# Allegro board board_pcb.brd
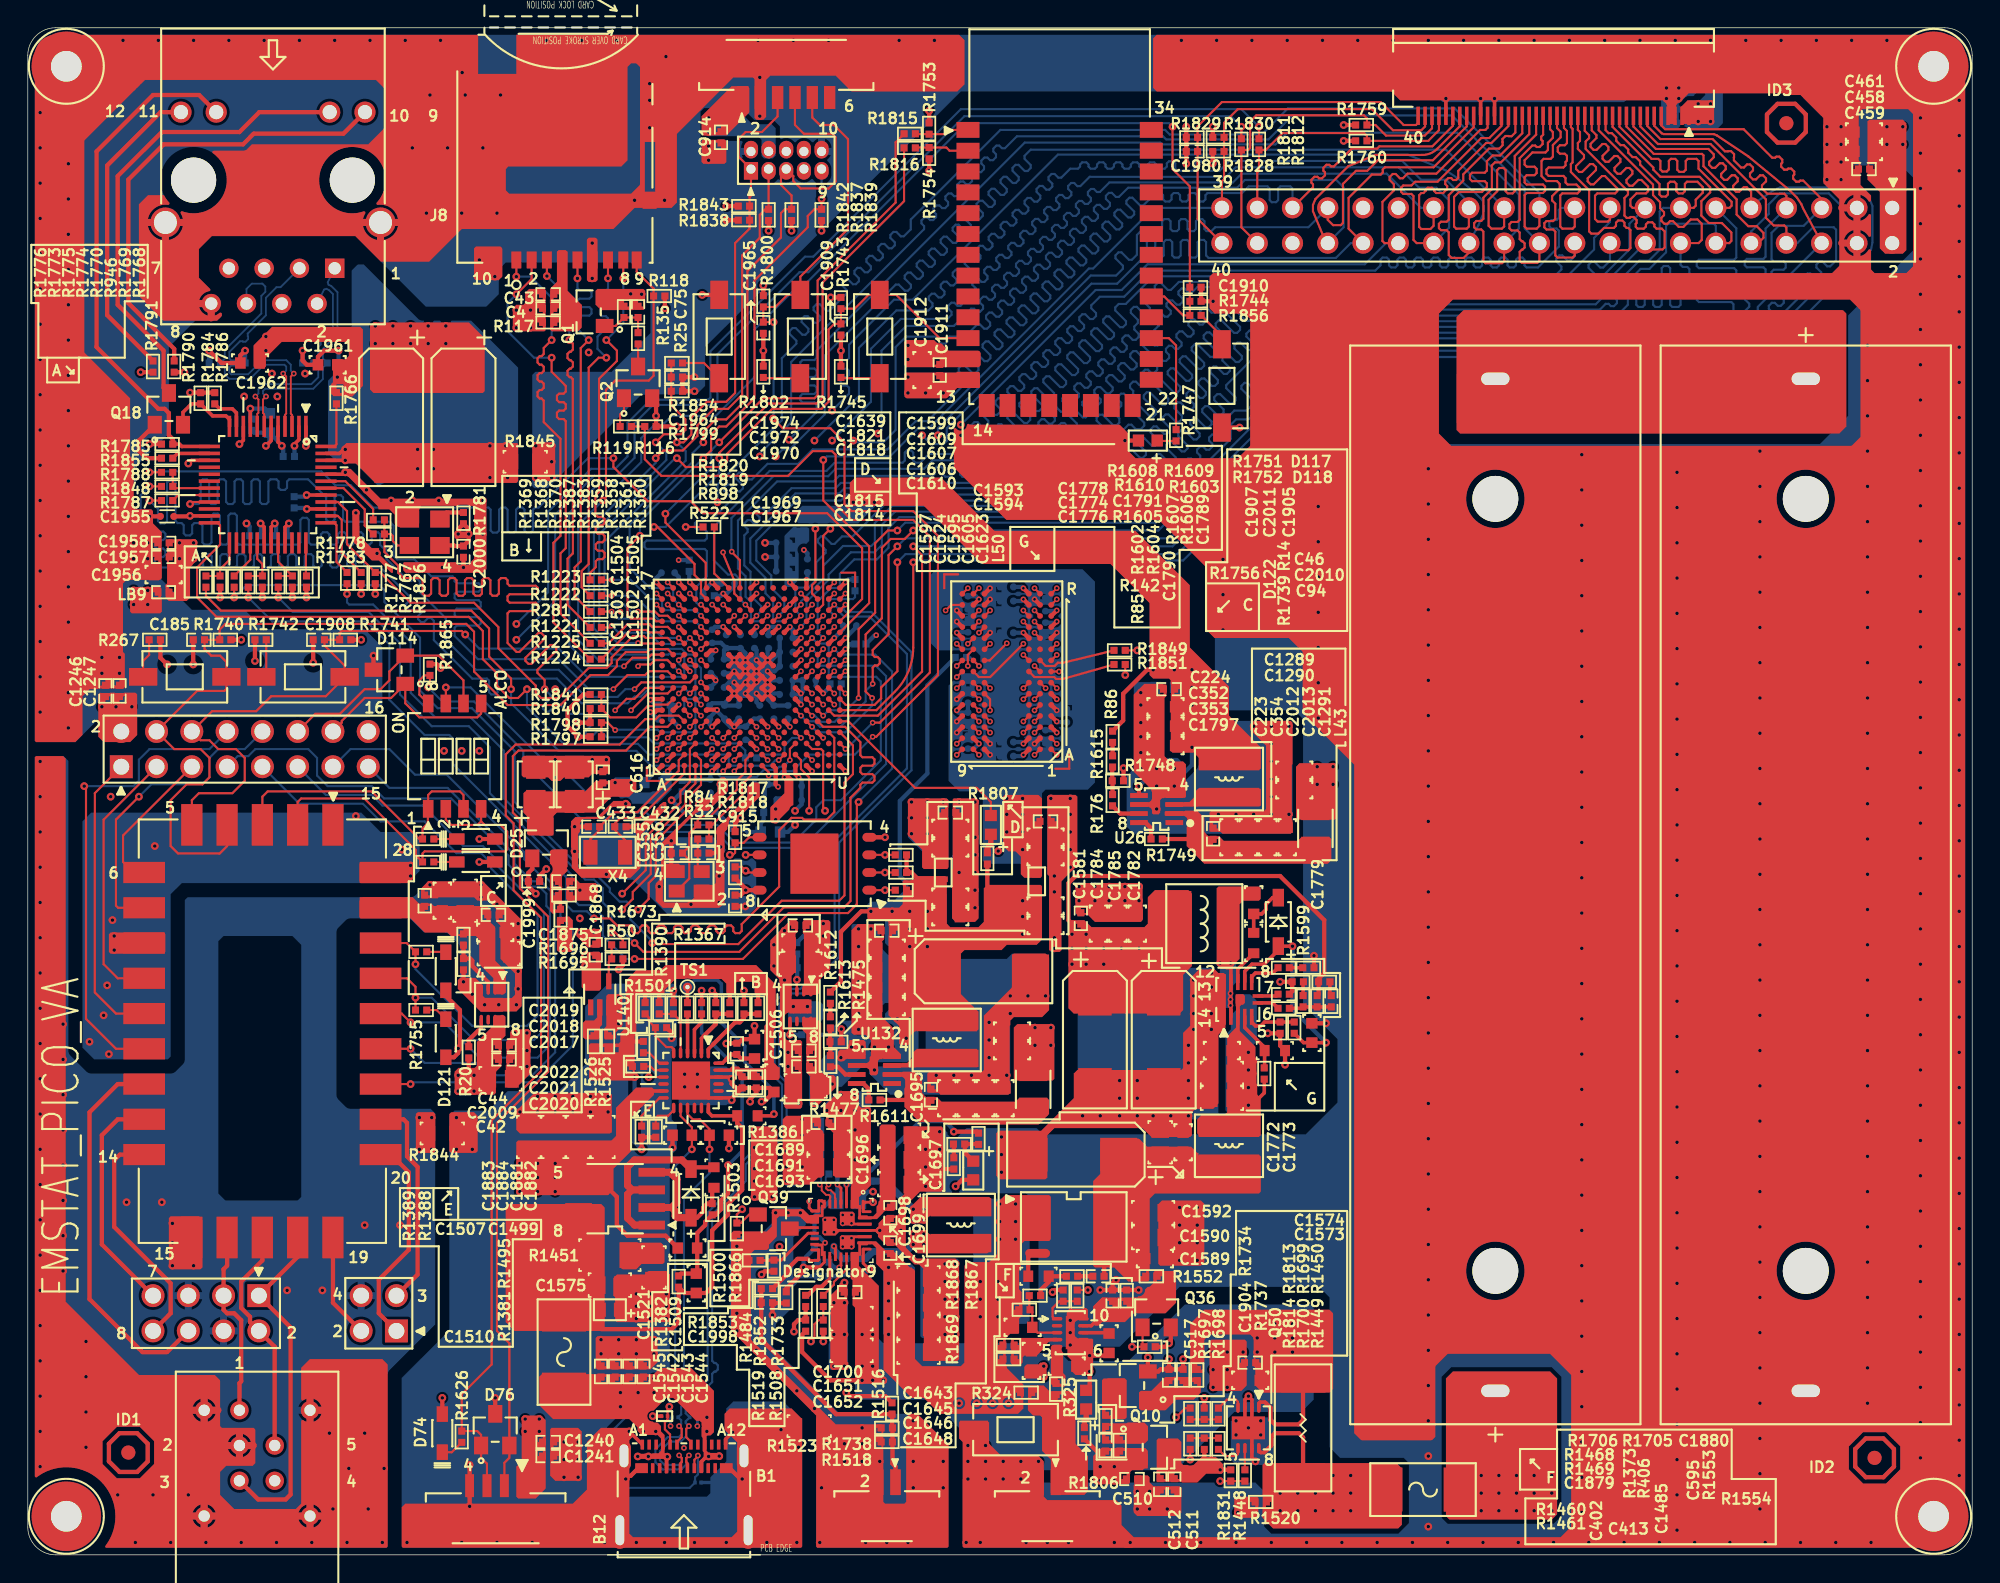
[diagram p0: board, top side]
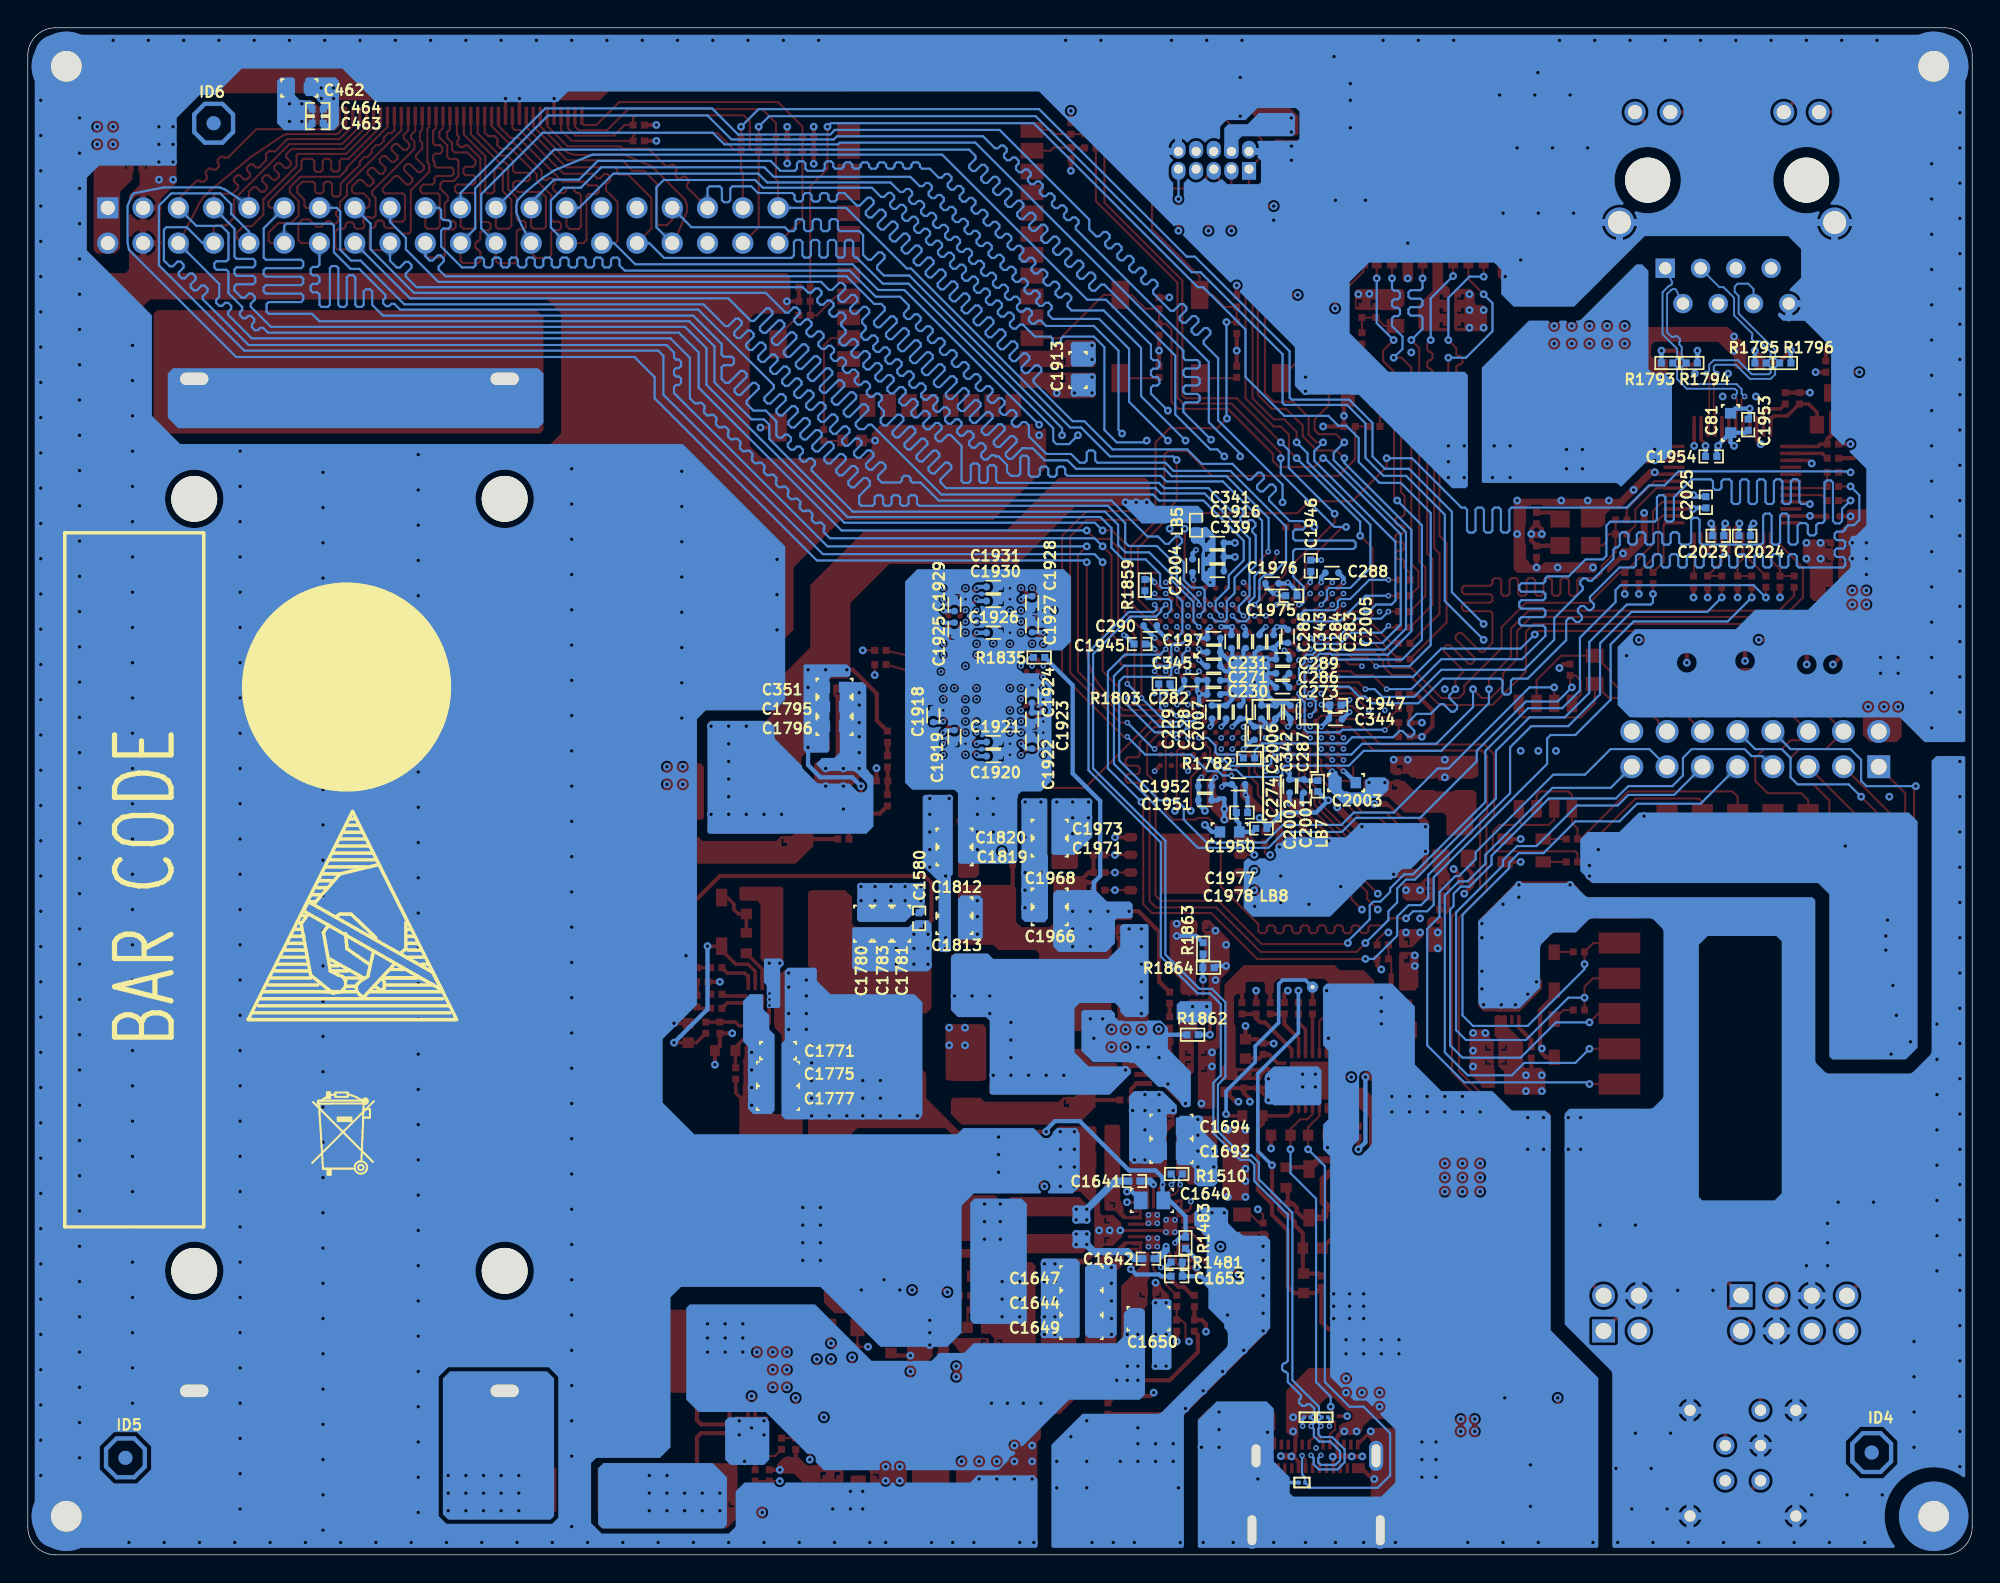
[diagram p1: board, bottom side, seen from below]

Outline 140 x 110 mm; copper layers: TOP, GND02, ART03, GND04, POWER05, ART06, GND07, ART08, GND09, BOTTOM. Coordinates in mm from the lower left corner of the outline.
Outline path: 0,108 0,2 arc(0.59,0.59) 2,0 138,0 arc(139.41,0.59) 140,2 140,108 arc(139.41,109.41) 138,110 2,110 arc(0.59,109.41) 0,108

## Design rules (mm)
constraint set DEFAULT: min track width 0.152
net group DIFF-USB: nets USB3_DM USB3_DP
net group DIFFPAIR0: nets RX+ RX-
net group DIFFPAIR1: nets TX+ TX-
net group DIFFPAIR2: nets BQ_DN BQ_DP
net group DIFFRX1_: nets RX1_N RX1_P
net group DIFFRX2_: nets RX2_N RX2_P
net group DIFFTX1_: nets TX1_N TX1_P
net group DIFFTX2_: nets TX2_N TX2_P
net group ETH_MDIO: nets ETH_MDIO N16775135
net group ETH_RMII_RXD0: nets ETH_RMII_RXD0 N16774923
net group ETH_RMII_RXD1: nets ETH_RMII_RXD1 N16774927
net group ETH_RMII_RXDV: nets ETH_RMII_RXDV N16776183
net group ETH_RMII_TXD0: nets ETH_RMII_TXD0 N16778460
net group FMC_A12: nets FMC_A12 N16908117
net group FMC_SDCKE0: nets FMC_SDCKE0 N16908318
net group PHY_INT: nets N16774766 PHY_INT
net group SDIO0_CCLK_OUT: nets N8887240 SDIO0_CCLK_OUT
net group SDIO0_CCMD: nets N8887398 SDIO0_CCMD
net group SDIO0_CDATA0: nets N8887325 SDIO0_CDATA0
net group SDIO0_CDATA1: nets N8887321 SDIO0_CDATA1
net group SDIO0_CDATA2: nets N8887299 SDIO0_CDATA2
net group SDIO0_CDATA3: nets N8887317 SDIO0_CDATA3
net group BUS_FMC_A: nets FMC_A0 FMC_A1 FMC_A2 FMC_A3 FMC_A4 FMC_A5 FMC_A6 FMC_A7 FMC_A8 FMC_A9 FMC_A10 FMC_A11 FMC_A14/FMC_BA0 FMC_A15/FMC_BA1 FMC_SDCLK FMC_SDNCAS FMC_SDNE0 FMC_SDNRAS FMC_SDNWE
net group ETH_RMII_CLK: nets ETH_RMII_CLK N16776304 N16872883
net group ETH_RMII_TXD1: nets ETH_RMII_TXD1 ETH_RMII_TXD1-1 N16778536
net group POWER: nets 1V2 3V3 3V9 5V0 AGND AVDD1V8 BQ_AGND GAUGE_PULLUP GND GND_SIGNAL N14944 N8915420 N8916004 N16783015 N16783029 N16886716 PHY_3V3 VBAT VBUS VBUS_MAX VBUS_MIN VBUS_OUT VCC_COMB VCC_SYS VCCD VDD1V2 VDD_MCU VDD_SDRAM VDDA3V3 VDDD VDDIO3V3_SD

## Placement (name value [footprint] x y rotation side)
C4  1uF  [SC0402]  37.47 89.79 180 top
C42  22uF  [SC0805]  34.04 34.29 0 top
C43  100nF  [SC0402]  37.47 90.81 180 top
C44  100nF  [SC0402]  34.29 36.7 180 top
C46  100nF  [SC0402]  33.53 46.1 180 top
C75  1uF  [SC0402]  43.94 89.53 270 top
C81  22uF  [SC0603]  17.4 81.53 270 bottom
C94  10uF  [SC0805]  33.91 43.31 0 top
C185  100nF  [SC0402]  12.32 65.91 180 top
C197  4.7uF  [SC0402-BGA]  54.61 66.04 180 bottom
C223  100nF  [SC0402]  85.34 51.94 270 top
C224  100nF  [SC0402]  82.17 62.36 0 top
C228  100nF  [SC0402-BGA]  53.72 60.71 270 bottom
C229  100nF  [SC0402-BGA]  54.74 60.71 270 bottom
C230  100nF  [SC0402-BGA]  54.61 61.98 0 bottom
C231  100nF  [SC0402-BGA]  54.61 64.01 0 bottom
C271  100nF  [SC0402-BGA]  54.61 62.99 0 bottom
C273  100nF  [SC0402-BGA]  49.66 62.48 180 bottom
C274  100nF  [SC0402-BGA]  51.69 59.18 90 bottom
C282  100nF  [SC0402-BGA]  56.26 62.99 180 bottom
C283  100nF  [SC0402-BGA]  50.29 65.79 90 bottom
C284  100nF  [SC0402-BGA]  51.31 65.79 90 bottom
C285  100nF  [SC0402-BGA]  53.34 65.79 90 bottom
C286  100nF  [SC0402-BGA]  49.66 63.5 180 bottom
C287  100nF  [SC0402-BGA]  49.1 60.71 270 bottom
C288  100nF  [SC0402-BGA]  46.1 70.74 0 bottom
C289  100nF  [SC0402-BGA]  49.66 64.52 180 bottom
C290  100nF  [SC0402-BGA]  59.18 66.93 0 bottom
C332  100uF  [SC7343]  26.16 81.79 270 top
C339  100nF  [SC0402-BGA]  54.36 70.87 0 bottom
C341  2.2uF  [SC0402-BGA]  54.36 72.9 180 bottom
C342  100nF  [SC0402-BGA]  50.16 60.71 270 bottom
C343  100nF  [SC0402-BGA]  52.32 65.79 90 bottom
C344  100nF  [SC0402-BGA]  45.85 60.2 180 bottom
C345  100nF  [SC0402-BGA]  54.61 65.02 0 bottom
C351  22uF  [SC0603]  81.92 62.48 180 bottom
C352  22uF  [SC0603]  81.92 61.09 180 top
C353  22uF  [SC0603]  81.92 59.69 180 top
C354  1uF  [SC0603]  86.49 51.69 270 top
C355  22pF  [SC0402]  46.74 50.55 0 top
C356  22pF  [SC0402]  48.64 50.55 180 top
C402  100nF  [SC0603]  72.26 13.97 270 top
C413  100nF  [SC0603]  74.8 13.59 0 top
C432  6pF  [SC0402]  42.67 52.45 180 top
C433  6pF  [SC0402]  40.77 52.45 0 top
C458  100nF  [SC0603]  132.21 101.09 0 top
C459  1uF  [SC0402]  132.21 99.82 180 top
C461  10uF  [SC0603]  132.21 102.49 180 top
C462  10uF  [SC0603]  120.45 105.66 180 bottom
C463  1uF  [SC0402]  119.13 103.12 180 bottom
C464  100nF  [SC0402]  119.13 104.14 0 bottom
C510  100nF  [SC0402]  79.5 5.46 0 top
C511  1uF  [SC0402]  82.55 5.08 270 top
C512  100nF  [SC0402]  81.53 5.08 270 top
C517  100nF  [SC0402]  82.17 12.95 90 top
C595  100nF  [SC0402]  78.11 18.67 90 top
C616  100nF  [SC0402]  41.4 56.01 270 top
C914  100nF  [SC0402]  49.91 102.11 90 top
C915  100nF  [SC0402]  50.93 47.12 270 top
C1240  1uF  [SC0402]  37.47 8.13 180 top
C1241  100nF  [SC0402]  37.47 7.11 0 top
C1246  1uF  [SC0402]  5.59 62.23 270 top
C1247  100nF  [SC0402]  6.6 62.23 90 top
C1289  22uF  [SC0603]  91.19 56.52 180 top
C1290  1uF  [SC0603]  91.19 55.12 0 top
C1291  22uF  [SC0603]  90.68 51.69 90 top
C1485  1uF  [SC0603]  77.85 15.24 90 top
C1499  390pF  [SC0603]  49.78 30.23 180 top
C1502  100nF  [SC0402]  52.45 34.04 90 top
C1503  100nF  [SC0402]  51.44 34.04 90 top
C1504  100nF  [SC0402]  51.05 36.45 270 top
C1505  1uF  [SC0603]  52.32 36.45 270 top
C1506  1uF  [SC0603]  53.72 34.04 90 top
C1507  390pF  [SC0603]  47.12 30.23 0 top
C1509  1uF  [SC0603]  48.13 19.56 90 top
C1510  1uF  [SC0603]  47.5 22.1 0 top
C1521  4.7uF  [SC0805]  45.09 20.7 270 top
C1542  10nF  [SC0402]  42.29 13.21 270 top
C1543  10nF  [SC0402]  43.31 13.21 270 top
C1544  10nF  [SC0402]  44.32 13.21 270 top
C1545  10nF  [SC0402]  41.27 13.21 270 top
C1573  1uF  [SC0603]  88.01 12.57 180 top
C1574  10nF  [SC0402]  88.01 13.84 0 top
C1575  4.7uF  [SC0805]  41.91 19.43 0 top
C1580  1uF  [SC0402]  75.82 45.85 90 bottom
C1581  100nF  [SC0402]  75.82 45.85 90 top
C1589  100nF  [SC0603]  81.15 21.34 180 top
C1590  10uF  [SC0805]  81.03 22.86 0 top
C1591  150uF  [SC7343]  75.31 28.83 180 top
C1592  10uF  [SC0805]  81.03 24.64 0 top
C1593  22uF  [SC0603]  70.87 37.72 180 top
C1594  1uF  [SC0603]  70.87 36.32 0 top
C1595  22uF  [SC0603]  67.56 32.89 90 top
C1597  100nF  [SC0402]  65.02 33.15 270 top
C1599  100nF  [SC0402]  61.85 44.96 0 top
C1605  22uF  [SC0603]  68.96 32.89 90 top
C1606  10uF  [SC0603]  61.85 40.89 180 top
C1607  10uF  [SC0603]  61.85 42.29 180 top
C1608  100uF  [SC7343]  68.96 42.04 0 top
C1609  10uF  [SC0603]  61.85 43.69 180 top
C1610  10uF  [SC0603]  61.85 39.5 180 top
C1623  22uF  [SC0603]  70.36 32.89 90 top
C1624  1uF  [SC0603]  66.17 32.89 270 top
C1639  100nF  [SC0402]  73.28 52.83 180 top
C1640  4.7uF  [SC0805]  59.05 25.53 0 bottom
C1641  47nF  [SC0402]  60.33 26.92 180 bottom
C1642  47nF  [SC0402]  59.31 21.34 180 bottom
C1643  10uF  [SC0805]  64.14 19.94 0 top
C1644  10uF  [SC0805]  64.14 18.16 0 bottom
C1645  10uF  [SC0805]  64.14 18.16 0 top
C1646  10uF  [SC0805]  64.14 16.38 0 top
C1647  10uF  [SC0805]  64.14 19.94 0 bottom
C1648  10uF  [SC0805]  64.14 14.61 0 top
C1649  10uF  [SC0805]  64.14 16.38 0 bottom
C1650  10uF  [SC0805]  59.31 17.02 180 bottom
C1651  10uF  [SC0805]  59.31 17.02 180 top
C1652  10uF  [SC0805]  59.31 14.73 180 top
C1653  1nF  [SC0402]  57.28 20.07 180 bottom
C1689  100nF  [SC0402]  57.28 31.11 180 top
C1691  10uF  [SC0805]  57.66 29.72 180 top
C1692  10uF  [SC0805]  57.66 29.08 180 bottom
C1693  10uF  [SC0805]  57.66 27.94 180 top
C1694  10uF  [SC0805]  57.66 30.86 180 bottom
C1695  10uF  [SC0805]  62.74 30.23 0 top
C1696  10uF  [SC0805]  62.74 28.45 0 top
C1697  10uF  [SC0805]  62.74 26.67 0 top
C1698  100nF  [SC0402]  62.1 24.64 270 top
C1699  100nF  [SC0402]  62.1 22.1 90 top
C1700  100nF  [SC0402]  59.18 18.92 180 top
C1771  1uF  [SC0603]  85.98 36.32 0 bottom
C1772  22uF  [SC0805]  81.53 29.72 90 top
C1773  1uF  [SC0603]  83.19 29.72 270 top
C1774  22uF  [SC0805]  85.98 34.67 180 top
C1775  22uF  [SC0805]  85.98 34.67 180 bottom
C1776  22uF  [SC0805]  85.98 32.89 180 top
C1777  22uF  [SC0805]  85.98 32.89 180 bottom
C1778  100nF  [SC0603]  85.98 36.32 0 top
C1779  100nF  [SC0603]  88.27 46.86 270 top
C1780  22uF  [SC0603]  79.88 45.47 90 bottom
C1781  22uF  [SC0603]  77.09 45.47 90 bottom
C1782  22uF  [SC0603]  79.88 45.47 90 top
C1783  22uF  [SC0603]  78.49 45.47 90 bottom
C1784  22uF  [SC0603]  77.09 45.47 90 top
C1785  22uF  [SC0603]  78.49 45.47 90 top
C1786  150uF  [SC7343]  76.83 36.96 270 top
C1788  150uF  [SC7343]  81.79 36.96 270 top
C1789  100nF  [SC0402]  93.85 39.88 90 top
C1790  100nF  [SC0603]  92.46 37.59 270 top
C1791  100nF  [SC0402]  90.42 40.39 180 top
C1795  22uF  [SC0603]  81.92 61.09 180 bottom
C1796  22uF  [SC0603]  81.92 59.69 180 bottom
C1797  22uF  [SC0603]  81.92 58.29 180 top
C1812  10uF  [SC0603]  73.28 46.74 0 bottom
C1813  22uF  [SC0603]  73.28 45.34 0 bottom
C1814  22uF  [SC0603]  73.28 45.34 0 top
C1815  1uF  [SC0603]  73.28 46.74 180 top
C1818  22uF  [SC0603]  73.28 50.29 0 top
C1819  22uF  [SC0603]  73.28 50.29 0 bottom
C1820  10uF  [SC0603]  73.28 51.69 0 bottom
C1821  1uF  [SC0603]  73.28 51.69 180 top
C1868  100nF  [SC0402]  40.89 43.59 90 top
C1875  100nF  [SC0402]  38.61 48.51 180 top
C1879  220nF  [SC0603]  71.63 16.38 180 top
C1880  47nF  [SC0402]  77.09 20.07 180 top
C1881  10uF  [SC0805]  39.62 30.1 90 top
C1882  10uF  [SC0805]  41.4 30.1 90 top
C1883  10uF  [SC0805]  36.07 30.1 90 top
C1884  10uF  [SC0805]  37.85 30.1 90 top
C1904  1uF  [SC0402]  77.6 7.87 90 top
C1905  10uF  [SC0805]  31.5 47.12 90 top
C1907  100nF  [SC0402]  28.57 47.12 270 top
C1908  100nF  [SC0402]  20.95 65.91 180 top
C1909  100nF  [SC0402]  58.55 88.27 270 top
C1910  100nF  [SC0402]  84.07 91.31 0 top
C1911  100nF  [SC0402]  65.66 85.34 90 top
C1912  10uF  [SC0603]  64.39 85.34 270 top
C1913  10uF  [SC0603]  64.39 85.34 270 bottom
C1916  470nF  [SC0402-BGA]  54.36 71.88 180 bottom
C1918  100nF  [SC0402-BGA]  74.8 60.45 90 bottom
C1919  100nF  [SC0402-BGA]  73.28 58.93 270 bottom
C1920  100nF  [SC0402-BGA]  70.48 57.53 180 bottom
C1921  100nF  [SC0402-BGA]  70.48 58.55 180 bottom
C1922  100nF  [SC0402-BGA]  67.69 58.55 90 bottom
C1923  100nF  [SC0402-BGA]  67.69 60.2 270 bottom
C1924  100nF  [SC0402-BGA]  67.69 61.85 90 bottom
C1925  100nF  [SC0402-BGA]  73.28 66.67 270 bottom
C1926  100nF  [SC0402-BGA]  70.48 66.42 180 bottom
C1927  100nF  [SC0402-BGA]  67.69 66.93 90 bottom
C1928  100nF  [SC0402-BGA]  67.69 68.58 270 bottom
C1929  100nF  [SC0402-BGA]  73.28 68.45 90 bottom
C1930  100nF  [SC0402-BGA]  70.48 68.71 180 bottom
C1931  100nF  [SC0402-BGA]  70.48 69.72 180 bottom
C1945  2.2uF  [SC0402]  59.94 65.61 180 bottom
C1946  2.2uF  [SC0402]  47.62 71.25 270 bottom
C1947  2.2uF  [SC0402]  45.85 61.21 180 bottom
C1950  470nF  [SC0402-BGA]  52.83 55.5 180 bottom
C1951  1uF  [SC0402-BGA]  55.24 54.36 0 bottom
C1952  100nF  [SC0402-BGA]  55.24 55.37 180 bottom
C1953  100nF  [SC0402]  16.13 81.41 90 bottom
C1954  100nF  [SC0402]  18.8 79.12 0 bottom
C1955  100nF  [SC0402-BGA]  10.03 74.8 0 top
C1956  10uF  [SC0603]  9.78 70.61 180 top
C1957  1uF  [SC0402]  9.78 71.88 180 top
C1958  100nF  [SC0402]  9.78 72.9 0 top
C1961  100nF  [SC0603]  21.59 85.72 180 top
C1962  100nF  [SC0603]  16 85.85 180 top
C1964  100nF  [SC0402]  46.74 84.84 0 top
C1965  100nF  [SC0402]  52.96 88.39 270 top
C1966  22uF  [SC0603]  66.42 45.97 0 bottom
C1967  22uF  [SC0603]  66.42 45.97 0 top
C1968  10uF  [SC0603]  66.42 47.37 0 bottom
C1969  1uF  [SC0603]  66.42 47.37 180 top
C1970  22uF  [SC0603]  66.42 50.93 0 top
C1971  22uF  [SC0603]  66.42 50.93 0 bottom
C1972  10uF  [SC0603]  66.42 52.32 0 top
C1973  1uF  [SC0603]  66.42 52.32 180 bottom
C1974  100nF  [SC0402]  66.42 53.47 180 top
C1975  1uF  [SC0402]  49.02 69.09 0 bottom
C1976  100nF  [SC0402-BGA]  50.42 69.98 180 bottom
C1977  1uF  [SC0402]  52.58 53.47 180 bottom
C1978  100nF  [SC0603]  53.47 52.07 180 bottom
C1980  100nF  [SC0402]  83.82 101.09 180 top
C1998  1nF  [SC0402]  53.21 18.16 0 top
C1999  100nF  [SC0402]  36.45 48.51 0 top
C2000  100nF  [SC0402]  31.37 72.26 90 top
C2001  4.7uF  [SC0402-BGA]  48.13 55.37 270 bottom
C2002  100nF  [SC0402-BGA]  49.15 55.37 90 bottom
C2003  100nF  [SC0603]  45.09 55.63 0 bottom
C2004  100nF  [SC0402-BGA]  56.13 71.25 270 bottom
C2005  100nF  [SC0402-BGA]  49.28 66.17 90 bottom
C2006  100nF  [SC0402-BGA]  51.18 60.71 270 bottom
C2007  100nF  [SC0402-BGA]  52.7 60.71 270 bottom
C2008  100uF  [SC7343]  31.37 81.79 270 top
C2009  1uF  [SC0402]  34.29 35.69 0 top
C2010  1uF  [SC0603]  33.66 44.83 180 top
C2011  1uF  [SC0603]  29.84 47.12 270 top
C2012  10uF  [SC0603]  87.88 51.69 90 top
C2013  10uF  [SC0603]  89.28 51.69 90 top
C2015  -  [CPH3225A]  36.58 55.5 90 top
C2016  -  [CPH3225A]  39.37 55.5 90 top
C2017  10uF  [SC0805]  55.63 42.55 180 top
C2018  1uF  [SC0603]  55.63 44.07 0 top
C2019  100nF  [SC0402]  55.63 45.34 0 top
C2020  22uF  [SC0805]  56.01 33.78 180 top
C2021  1uF  [SC0402]  55.88 35.18 180 top
C2022  100nF  [SC0402]  55.88 36.32 0 top
C2023  100nF  [SC0402]  18.29 73.41 180 bottom
C2024  100nF  [SC0402]  16.38 73.41 0 bottom
C2025  100nF  [SC0402]  19.18 75.82 90 bottom
D25  BAS70-05  [SOT23]  37.34 51.31 0 top
D74  BAT60BE6327  [HSOD323A]  29.84 8.76 270 top
D76  PSOT05C  [SOT23]  33.66 9.02 0 top
D96  uClamp2271P  [DFN16X10X050X2LEAD]  41.91 17.65 0 top
D97  NZH10C,115  [SOD123F]  47.75 26.04 270 top
D106  RClamp3371ZC  [DFN_060X030X025MM_2LEAD]  48.26 5.21 0 bottom
D107  RClamp3371ZC  [DFN_060X030X025MM_2LEAD]  45.85 9.99 180 top
D108  RClamp3371ZC  [DFN_060X030X025MM_2LEAD]  47.88 9.91 0 bottom
D109  RClamp3371ZC  [DFN_060X030X025MM_2LEAD]  46.61 9.91 180 bottom
D112  BAV16W  [SOD123]  90.04 45.59 90 top
D113  LSM0603412V  [SLED0603]  80.64 80.26 0 top
D114  PSOT05C  [SOT23]  26.04 63.75 90 top
D117  BAT60BE6327  [HSOD323A]  32.26 51.56 180 top
D118  BAT60BE6327  [HSOD323A]  32.26 49.91 180 top
D121  BAT60BE6327  [HSOD323A]  30.1 37.21 90 top
D122  BAT60BE6327  [HSOD323A]  30.1 42.04 90 top
D132  LSM0603412V  [SLED0603]  69.34 52.58 270 top
D133  LSM0603453V  [SLED0603]  76.2 11.18 270 top
D134  LSM0603453V  [SLED0603]  68.07 27.69 90 top
F1  SSQ8  [CRF1206-FX-R020ELF]  100.46 4.7 0 top
F4  SSQ8  [CRF1206-FX-R020ELF]  38.61 14.61 90 top
J1  FH12-40S-0.5SH(54)  [FPC-40P_05MM]  109.86 105.28 0 top
J2  2X20P_40P_2_54MM  [DIP_2X20X_254]  110.11 95.76 180 top
J3  -  [HR911105A]  17.65 97.03 0 top
J5  BAT_CONNECTOR  [BAT_CONNECTOR_18650]  105.66 48.26 270 top
J6  1.25T-1-WT-6A  [1P25MM-6PIN]  54.61 106.43 0 top
J7  BAT_CONNECTOR  [BAT_CONNECTOR_18650]  128.02 48.26 90 top
J8  DM3AT_SF_PEJM5  [HSDC10-1614B]  37.95 101.25 180 top
J56  -  [1P27MM-10PIN]  54.61 100.46 0 top
J63  1.25T-1-LT-4A  [4PIN-1P25MM]  33.69 3.53 0 top
J73  2012670005  [USB_C_24P]  47.24 4.66 0 top
J74  67996-104HLF  [2X2PIN_254MM]  25.27 17.4 90 top
J75  -  [EPG_0B_305_HLN]  16.51 6.6 270 top
J76  826632-4  [8PIN_254MM]  12.83 17.4 180 top
J78  67996-116HLF  [2X8PIN_254MM]  15.62 58.04 0 top
J85  1.25T-1-LT-2A  [2PIN_125MM]  61.85 3.68 180 top
J86  1.25T-1-LT-2A  [2PIN_125MM]  73.41 3.68 180 top
L10  1uH  [XEL4030]  86.49 55.88 90 top
L43  1uH  [SL1008H]  92.71 52.32 270 top
L50  1uH  [SL1008H]  72.39 33.53 270 top
L53  1uH  [XEL4030]  66.17 37.08 90 top
L54  1uH  [XEL4030]  67.18 23.75 90 top
L59  1uH  [XEL4030]  86.49 29.46 90 top
L60  1uH  [XAL5030]  84.71 45.47 180 top
L61  18nH  [PFL1005]  72.64 48.51 90 top
L63  18nH  [PFL1005]  65.91 49.15 90 top
LB5  BLM15HG102SN1D  [SL0402]  55.88 74.17 270 bottom
LB7  BLM15HG102SN1D  [SL0402]  47.12 55.37 90 bottom
LB8  BLM15HG102SN1D  [SL0402]  51.18 52.32 0 bottom
LB9  BLM15HG102SN1D  [SL0402]  9.78 69.34 0 top
M1  -  [HOLE87-197]  137.22 107.22 0 top
M2  -  [HOLE87-197]  2.78 107.22 0 top
M3  -  [HOLE87-197]  137.22 2.78 0 top
M4  -  [HOLE87-197]  2.78 2.78 0 top
NOREF  -  []  2 110 0 top
NOREF#2  -  []  162.9 151.25 0 top
NOREF#3  -  []  47.6 201.98 0 top
NOREF#4  -  [unnamed#2]  132.97 6.99 0 top
NOREF#5  -  []  158.62 225.3 0 top
NOREF#6  -  [unnamed#2]  126.62 103.12 0 top
NOREF#7  -  []  0 0 0 top
NOREF#8  -  []  140 2 0 top
NOREF#9  -  []  -53.9 -55.37 0 top
NOREF#10  -  [unnamed#2]  7.24 7.37 0 top
NOREF#11  -  []  0 0 0 top
NOREF#12  -  []  71.15 144.3 0 top
NOREF#13  -  []  116.1 45.54 180 bottom
NOREF#14  -  []  117.17 62.76 180 bottom
NOREF#15  -  [unnamed#2]  126.62 103.12 180 bottom
NOREF#16  -  []  132.26 49.02 90 bottom
NOREF#17  -  [unnamed#2]  132.97 6.99 180 bottom
NOREF#18  -  [unnamed#2]  7.24 7.37 180 bottom
NOREF#19  -  []  114.76 30.45 180 bottom
Q1  SI2305CDS-T1-GE3  [SOT23]  40.39 89.53 90 top
Q2  BSS806NE  [SOT23]  43.94 84.45 0 top
Q10  BSS806NE  [SOT23]  79.5 12.19 90 top
Q18  S8050LTI  [SOT23]  10.16 82.55 0 top
Q22  IRF9358TRPBF  [8-SOIC]  42.29 25.65 90 top
Q35  BSO080P03S H  [INF-PG-DSO-8-3_N]  75.31 23.62 0 top
Q36  BSS806NE  [SOT23]  81.28 17.53 0 top
Q39  BSS806NE  [SOT23]  53.72 23.5 270 top
Q50  SI2305CDS-T1-GE3  [SOT23]  81.15 7.75 270 top
R14  68K  [SR0402]  31.37 44.32 270 top
R20  10K  [SR0402]  31.75 36.2 90 top
R25  100  [SR0402]  43.94 87.63 270 top
R32  100  [SR0402]  48.64 51.56 0 top
R50  30K  [SR0402]  42.44 42.93 0 top
R84  1M  [SR0402]  48.64 52.58 0 top
R85  100K  [SR0402]  89.03 34.67 90 top
R86  100K  [SR0402]  78.11 58.93 270 top
R116  10K  [SR0402]  44.83 81.28 0 top
R117  10K  [SR0402]  37.47 88.77 180 top
R118  10K  [SR0402]  45.47 90.68 180 top
R119  2K  [SR0402]  43.05 81.28 0 top
R135  2K  [SR0402]  42.93 89.53 270 top
R142  49.9K  [SR0603]  89.79 36.32 0 top
R176  0  [SR0402]  78.11 54.36 90 top
R267  100  [SR0402]  9.14 65.91 0 top
R281  33  [SR0402]  40.89 67.94 0 top
R324  10K  [SR0402]  71.88 11.68 0 top
R325  4.7K  [SR0402]  74.04 11.94 90 top
R406  33  [SR0402]  75.56 18.67 270 top
R522  0  [SR0402]  49.02 74.04 0 top
R898  10K  [SR0402]  62.87 47.88 180 top
R946  120  [SR0402]  18.03 70.1 270 top
R1221  33  [SR0402]  40.89 66.8 0 top
R1222  33  [SR0402]  40.89 69.09 0 top
R1223  33  [SR0402]  40.89 70.23 0 top
R1224  33  [SR0402]  40.89 64.52 0 top
R1225  33  [SR0402]  40.89 65.66 0 top
R1358  5.1K  [SR0402]  50.55 39.37 90 top
R1359  2.43K  [SR0402]  49.53 39.37 90 top
R1360  5.1K  [SR0402]  52.58 39.37 90 top
R1361  1K  [SR0402]  51.56 39.37 270 top
R1367  0  [SR0402]  45.59 37.97 0 top
R1368  5.1K  [SR0402]  45.47 39.37 90 top
R1369  5.1K  [SR0402]  44.45 39.37 90 top
R1370  5.1K  [SR0402]  46.48 39.37 270 top
R1373  4.7K  [SR0402]  74.55 18.67 90 top
R1381  0  [SR0402]  49.28 24.89 270 top
R1382  10K  [SR0402]  46.86 19.68 90 top
R1383  1K  [SR0402]  48.51 39.37 90 top
R1386  49.9K  [SR0603]  51.82 31.62 0 top
R1387  1K  [SR0402]  47.5 39.37 90 top
R1388  2K  [SR0402]  45.21 30.48 270 top
R1389  2K  [SR0402]  44.2 30.48 270 top
R1390  2K  [SR0402]  44.32 36.58 90 top
R1446  0.01  [SR2512]  91.82 9.14 90 top
R1448  33  [SR0402]  87.63 5.71 90 top
R1449  33  [SR0402]  85.72 8 270 top
R1450  33  [SR0402]  85.72 10.16 90 top
R1451  5.6  [SR1206]  41.91 21.59 180 top
R1460  2K  [SR0402]  70.61 15.11 0 top
R1461  2K  [SR0402]  70.61 14.1 180 top
R1468  100K  [SR0402]  72.52 18.67 180 top
R1469  100K  [SR0402]  71.75 17.65 0 top
R1475  5.1K  [SR0402]  58.17 36.96 0 top
R1477  0  [SR0402]  57.78 35.56 90 top
R1481  6.04K  [SR0402]  57.28 21.08 180 bottom
R1483  100K  [SR0402]  56.64 22.48 270 bottom
R1484  180K  [SR0402]  54.61 18.54 270 top
R1495  49.9K  [SR0603]  49.4 27.18 270 top
R1500  12K  [SR0402]  52.32 21.21 0 top
R1501  2K  [SR0402]  43.94 35.18 0 top
R1503  10K  [SR0402]  51.05 23.5 270 top
R1508  10K  [SR0402]  57.28 16.51 90 top
R1510  0  [SR0402]  57.28 27.43 0 bottom
R1516  5.23K  [SR0402]  62.23 10.54 270 top
R1518  30K  [SR0402]  61.85 8.13 0 top
R1519  0  [SR0402]  56.01 16.51 90 top
R1520  0  [SR0402]  88.77 3.81 0 top
R1523  10  [SR0805]  56.26 9.27 180 top
R1525  10K  [SR0402]  41.78 36.98 90 top
R1526  100  [SR0402]  40.77 36.98 90 top
R1552  180K  [SR0402]  80.9 20.07 180 top
R1553  30K  [SR0402]  79.12 18.67 90 top
R1554  4.7K  [SR0402]  80.77 14.99 180 top
R1599  10  [SR0603]  88.27 44.07 90 top
R1602  4.7K  [SR0402]  90.17 37.97 270 top
R1603  4.7K  [SR0402]  93.34 41.27 0 top
R1604  4.7K  [SR0402]  91.19 37.97 270 top
R1605  12.7K  [SR0402]  90.42 39.37 0 top
R1606  22.1K  [SR0402]  92.84 39.88 90 top
R1607  2K  [SR0402]  91.82 39.88 90 top
R1608  10K  [SR0402]  90.42 42.29 180 top
R1609  4.7K  [SR0402]  92.2 42.29 0 top
R1610  1K  [SR0402]  91.44 41.27 180 top
R1611  4.7K  [SR0402]  60.96 32.77 180 top
R1612  22.1K  [SR0402]  57.78 40.13 270 top
R1613  1.5K  [SR0402]  57.78 38.35 90 top
R1615  2K  [SR0402]  78.11 57.15 270 top
R1626  4.7K  [SR0402]  31.24 8.51 90 top
R1673  33  [SR0402]  42.44 43.94 0 top
R1695  22.1K  [SR0402]  38.35 46.1 270 top
R1696  10K  [SR0402]  38.61 47.5 0 top
R1697  20K  [SR0402]  83.19 12.95 90 top
R1698  20K  [SR0402]  84.2 12.95 90 top
R1699  4.7K  [SR0402]  84.71 10.16 90 top
R1700  4.7K  [SR0402]  84.71 8 270 top
R1705  2K  [SR0402]  75.18 20.07 0 top
R1706  10  [SR0603]  72.77 20.07 180 top
R1733  33  [SR0402]  57.28 18.29 270 top
R1734  100  [SR0402]  77.6 9.65 90 top
R1737  2K  [SR0402]  78.61 7.87 90 top
R1738  10K  [SR0402]  61.85 9.14 180 top
R1739  10K  [SR0402]  31.37 42.55 270 top
R1740  10K  [SR0402]  14.22 65.91 180 top
R1741  10K  [SR0402]  22.86 65.91 180 top
R1742  100  [SR0402]  16.76 65.91 180 top
R1743  10K  [SR0402]  58.55 90.17 270 top
R1744  10K  [SR0402]  84.07 90.3 0 top
R1745  100  [SR0402]  58.55 85.22 90 top
R1747  470  [SR0402]  82.68 80.64 270 top
R1748  100K  [SR0402]  78.49 55.75 0 top
R1749  4.7K  [SR0402]  81.28 51.56 180 top
R1751  10K  [SR0402]  28.83 51.56 180 top
R1752  10K  [SR0402]  28.83 49.91 180 top
R1753  4.7K  [SR0402]  64.9 102.74 270 top
R1754  4.7K  [SR0402]  64.9 100.97 90 top
R1755  4.7K  [SR0402]  28.32 39.24 180 top
R1756  4.7K  [SR0402]  28.32 43.43 180 top
R1759  4.7K  [SR0402]  96.01 103 0 top
R1760  4.7K  [SR0402]  96.01 101.85 0 top
R1766  6.8K 1%  [SR0402]  22.23 83.31 90 top
R1767  10K  [SR0402]  24 70.36 270 top
R1768  10K  [SR0402]  20.07 70.1 270 top
R1769  10K  [SR0402]  19.05 70.1 270 top
R1770  10K  [SR0402]  16.89 70.1 90 top
R1773  10K  [SR0402]  13.84 70.1 270 top
R1774  120  [SR0402]  15.88 70.1 270 top
R1775  120  [SR0402]  14.86 70.1 270 top
R1776  120  [SR0402]  12.83 70.1 270 top
R1777  120  [SR0402]  22.99 70.36 270 top
R1778  51  [SR0402]  25.27 74.55 0 top
R1781  1K  [SR0402]  31.37 74.68 270 top
R1782  51  [SR0402]  52.07 57.4 180 bottom
R1783  51  [SR0402]  25.27 73.53 0 top
R1784  10K  [SR0402]  12.45 83.31 90 top
R1785  10K  [SR0402]  10.03 80.01 180 top
R1786  10K  [SR0402]  13.46 83.31 90 top
R1787  120  [SR0402]  10.03 75.95 0 top
R1788  120  [SR0402]  10.03 76.96 0 top
R1790  510  [SR0402]  10.54 85.6 90 top
R1791  510  [SR0402]  9.02 85.6 90 top
R1793  49.9  [SR0402]  21.97 85.85 180 bottom
R1794  49.9  [SR0402]  20.19 85.85 0 bottom
R1795  49.9  [SR0402]  15.24 85.85 180 bottom
R1796  49.9  [SR0402]  13.46 85.85 0 bottom
R1797  10K  [SR0402]  40.89 58.93 0 top
R1798  10K  [SR0402]  40.89 59.94 0 top
R1799  10K  [SR0402]  46.74 83.82 0 top
R1800  10K  [SR0402]  52.96 90.3 270 top
R1802  100  [SR0402]  52.96 85.22 90 top
R1803  10K  [SR0402]  58.17 62.74 180 bottom
R1806  1K  [SR0402]  76.07 8.76 90 top
R1807  1K  [SR0402]  69.09 50.16 90 top
R1811  0  [SR0402]  87.38 101.6 90 top
R1812  0  [SR0402]  88.65 101.6 90 top
R1813  0  [SR0402]  83.69 10.16 90 top
R1814  0  [SR0402]  83.69 8 270 top
R1815  0  [SR0402]  63.5 102.36 180 top
R1816  0  [SR0402]  63.5 101.35 180 top
R1817  10K  [SR0402]  50.93 51.69 270 top
R1818  10K  [SR0402]  50.93 49.15 90 top
R1819  10K  [SR0402]  62.87 49.15 180 top
R1820  10K  [SR0402]  62.87 50.42 180 top
R1826  10K  [SR0402]  25.02 70.36 270 top
R1828  10K  [SR0402]  85.72 101.09 0 top
R1829  10K  [SR0402]  83.82 102.11 180 top
R1830  10K  [SR0402]  85.72 102.11 0 top
R1831  4.7K  [SR0402]  86.61 5.71 270 top
R1835  10K  [SR0402]  67.18 64.64 180 bottom
R1837  10K  [SR0402]  54.99 96.52 90 top
R1838  10K  [SR0402]  51.56 96.14 180 top
R1839  10K  [SR0402]  57.15 96.52 90 top
R1840  10K  [SR0402]  40.89 61.98 0 top
R1841  10K  [SR0402]  40.89 60.96 180 top
R1842  10K  [SR0402]  53.34 96.52 90 top
R1843  10K  [SR0402]  51.56 97.16 0 top
R1844  10  [SR0805]  29.84 30.35 180 top
R1845  10  [SR0805]  35.81 78.74 180 top
R1848  0  [SR0402]  10.03 77.98 0 top
R1849  0  [SR0402]  78.61 65.15 180 top
R1851  0  [SR0402]  78.61 64.14 180 top
R1852  100  [SR0402]  56.01 18.29 270 top
R1853  1K  [SR0402]  53.21 19.18 180 top
R1854  2K  [SR0402]  46.74 85.85 0 top
R1855  4.7K  [SR0402]  10.03 78.99 0 top
R1856  4.7K  [SR0402]  84.07 89.28 0 top
R1859  10K  [SR0402]  59.56 69.85 270 bottom
R1862  10K  [SR0402]  56.13 37.47 180 bottom
R1863  100K  [SR0402]  55.37 43.69 270 bottom
R1864  25K  [SR0402]  54.99 42.29 180 bottom
R1865  10K  [SR0402]  28.96 63.75 270 top
R1866  10K  [SR0402]  53.72 20.83 90 top
R1867  2K  [SR0402]  68.45 29.97 90 top
R1868  2K  [SR0402]  67.06 29.59 0 top
R1869  1K  [SR0402]  66.67 28.19 270 top
S3  SKQYAAE010  [SMT2]  11.3 63.25 0 top
S4  SKQYAAE010  [SMT2]  71.12 9.02 180 top
S5  SKQYAAE010  [SMT2]  19.81 63.25 0 top
S6  SKQYAAE010  [SMT2]  61.34 87.76 90 top
S7  SKQYAAE010  [SMT2]  85.98 84.2 270 top
S8  -  [1571983-4]  30.73 57.53 0 top
S10  SKQYAAE010  [SMT2]  49.78 87.76 90 top
S11  SKQYAAE010  [SMT2]  55.63 87.76 90 top
TS1  TEST  [GND12]  47.5 40.89 180 top
U1  STM32H743XIH6  [BGA265_0R8_14X14]  52.07 63.25 0 top
U2  IS42S32800G-6BLI  [FBGA90_0R8_8X13]  70.48 63.63 90 top
U3  DM9161EP  [LQFP48-0M5-JL]  17.27 77.09 180 top
U4  ADP125ACPZ-R7  [CP-8-10]  33.4 39.62 180 top
U8  MP2229GQ  [QFN-14]  87.12 40.01 0 top
U26  MP2143DJ  [TSOT23-8]  81.28 53.72 90 top
U37  LTC2955IDDB-2  [DFN10DDB]  75.06 16 270 top
U77  W25Q256JVEIQ  [WSON_8P_8X6MM]  56.64 49.78 90 top
U117  CYPD3177-24LQXQ  [QFN_24P]  47.75 34.16 180 top
U128  LTC2943IDD#PBF  [DFN_8P]  87.88 9.14 180 top
U132  MP2143DJ  [TSOT23-8]  60.96 34.92 90 top
U133  BQ25792RQMR  [RQM0029A-MFG]  58.55 23.37 270 top
U134  EMSTAT PICO  [EMSTAT_PICO]  16.89 37.72 270 top
U135  HC-06  [HC_06_34]  74.3 96.39 0 top
U140  SN74LVC1G07DCK  [HSOT-SC70-DCK]  41.18 40.37 0 top
U141  ADP125ACPZ-R7  [CP-8-10]  55.63 39.5 180 top
X3  XC22M4-25.000-F18LJDTY  [SMD_2520]  47.62 48.51 0 top
X4  -  [HSX2-0302]  41.76 50.61 0 top
X5  SIT8208AC-23-33E-50.000000  [SMD_3225]  28.57 73.66 180 top

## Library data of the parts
C4 C42-C44 C46 C75 C81 C94 C185 C197 C223 C224 C228-C231 C271 C273 C274 C282-C290 C339 C341-C345 C351-C356 C402 C413 C432 C433 C458 C459 C461-C464 C510-C512 C517 C595 C616 C914 C915 C1240 C1241 C1246 C1247 C1289-C1291 C1485 C1499 C1502-C1507 C1509 C1510 C1521 C1542-C1545 C1573-C1575 C1580 C1581 C1589 C1590 C1592-C1595 C1597 C1599 C1605-C1607 C1609 C1610 C1623 C1624 C1639-C1653 C1689 C1691-C1700 C1771-C1785 C1789-C1791 C1795-C1797 C1812-C1815 C1818-C1821 C1868 C1875 C1879-C1884 C1904 C1905 C1907-C1913 C1916 C1918-C1931 C1945-C1947 C1950-C1958 C1961 C1962 C1964-C1978 C1980 C1998-C2007 C2009-C2013 C2017-C2025 = C_1
C332 C1591 C1608 C1786 C1788 C2008 = CAP-OS
C2015 C2016 = CAP-OS-CON-F13_0
D25 = BAT54C_0
D74 D112 D113 D117 D118 D121 D122 D132-D134 = D_A_0
D76 D114 = D2-3_D
D96 D97 = DIODE ZENER
D106-D109 = RClamp3371ZC
F1 F4 = FUSE2
J1 = CON-FPC-40P_SMT_MOVEDOWN0_0
J2 = CON-LCD_2X20P_40P_2_54MM_TC_0
J3 = CN-NET_T_RJ45_HR911105A_HIDE_0
J5 J7 = BAT_CONNECTOR
J6 = 1_0.25T-1-LT-8A
J8 = SIMM10S4_B_0
J56 = 1P27MM-10PIN
J63 = 1.25T-1-LT-4A
J73 = 2012670005
J74 = Header 2X2
J75 = EPG_0B_305_HLN_0
J76 = Header 8
J78 = Header 8X2
J85 J86 = KF2EDGR-2.54
L10 L43 L50 L53 L54 L59-L61 L63 = IND
LB5 LB7-LB9 = LB_0
M1-M4 = HOLE-8STARS_2
Q1 Q50 = FETP-GSD_0
Q2 Q10 Q36 Q39 = NTR4503N
Q18 = 2N2222
Q22 = MOSFET_N_GDS_0
Q35 = BSO201SP H
R14 R20 R84-R86 R116-R119 R135 R142 R176 R324 R325 R406 R522 R898 R1358-R1361 R1367-R1370 R1373 R1381-R1383 R1386-R1390 R1448-R1451 R1460 R1461 R1468 R1469 R1475 R1477 R1483 R1484 R1495 R1500 R1501 R1503 R1508 R1510 R1516 R1519 R1520 R1523 R1525 R1552 R1554 R1599 R1602-R1613 R1615 R1626 R1673 R1695-R1700 R1705 R1706 R1733 R1737-R1741 R1743 R1744 R1748 R1749 R1751-R1756 R1759 R1760 R1766-R1770 R1773 R1778 R1781 R1784-R1786 R1790 R1791 R1793-R1800 R1803 R1806 R1807 R1811-R1820 R1826 R1828-R1831 R1835 R1837-R1845 R1853-R1856 R1859 R1862-R1869 = R
R25 R32 R50 R267 R1446 R1481 R1518 R1526 R1553 R1734 R1742 R1745 R1747 R1802 R1852 = R_0
R281 R1221-R1225 = R: signal model: RC0402FR-0733RL_33
R946 R1774-R1777 R1787 R1788 = R: signal model: RC0402FR-07120RL_120
R1782 R1783 = R: signal model: RC0402FR-0751RL_51
R1848 R1849 R1851 = R: signal model: RC0402JR_070RL_0
S3-S7 S10 S11 = SW_PB_SPST
S8 = SW DIP-6_0
TS1 = TEST
U1 = STM32H7_TFBGA265_18
U2 = IS42S32800G-6BLI_TF-BGA-90_2
U3 = U-DM9161_QPF48-0_1
U4 U141 = ADP125ACPZ-R7_0
U8 = MP2229GQ
U26 U132 = MP2143_0
U37 = LTC2955IDDB-DFN10DDB_0
U77 = N25Q032A11ESE40F_0
U117 = CYPD3177-24LQXQ
U128 = LTC2943IDD#PBF
U133 = BQ25792RQMR
U134 = EmStat pico_0
U135 = HC-06_0
U140 = SN74LVC1G07DCK
X3 = X_B_0
X4 = X_0_HSX2-0302_32.768KHZ
X5 = TMP_162231

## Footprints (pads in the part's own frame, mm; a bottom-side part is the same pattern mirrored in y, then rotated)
1P25MM-6PIN
  rect 2.108x2.997 smd: (-5.675,1.45) (5.675,1.45)
  rect 0.813x1.651 smd: 1(-3.125,-1.45) 2(-1.875,-1.45) 3(-0.625,-1.45) 4(0.625,-1.45) 5(1.875,-1.45) 6(3.125,-1.45)
1P27MM-10PIN
  rect 1.016x1.27 hole 0.66: 1(-2.54,-0.635)
  oval 1.016x1.27 hole 0.66: 2(-2.54,0.635) 3(-1.27,-0.635) 4(-1.27,0.635) 5(0,-0.635) 6(0,0.635) 7(1.27,-0.635) 8(1.27,0.635) 9(2.54,-0.635) 10(2.54,0.635)
2PIN_125MM
  rect 2.108x3.251 smd: (-3.175,1.45) (3.175,1.45)
  rect 0.762x1.854 smd: 1(-0.625,-1.55) 2(0.625,-1.55)
2X2PIN_254MM
  rect 1.651x1.651 hole 1.143: 1(-1.27,-1.27)
  round 1.651 hole 1.143: 2(-1.27,1.27) 3(1.27,-1.27) 4(1.27,1.27)
2X8PIN_254MM
  rect 1.651x1.651 hole 1.143: 1(-8.89,-1.27)
  round 1.651 hole 1.143: 2(-8.89,1.27) 3(-6.35,-1.27) 4(-6.35,1.27) 5(-3.81,-1.27) 6(-3.81,1.27) 7(-1.27,-1.27) 8(-1.27,1.27) 9(1.27,-1.27) 10(1.27,1.27) 11(3.81,-1.27) 12(3.81,1.27) 13(6.35,-1.27) 14(6.35,1.27) 15(8.89,-1.27) 16(8.89,1.27)
4PIN-1P25MM
  rect 2.159x2.997 smd: (-4.425,-1.45) (4.425,-1.45)
  rect 0.635x1.651 smd: 1(1.875,1.45) 2(0.625,1.45) 3(-0.625,1.45) 4(-1.875,1.45)
8-SOIC
  rect 0.635x1.905 smd: 1(-1.905,-2.632) 2(-0.635,-2.632) 3(0.635,-2.632) 4(1.905,-2.632) 5(1.905,2.632) 6(0.635,2.632) 7(-0.635,2.632) 8(-1.905,2.632)
8PIN_254MM
  rect 1.651x1.651 hole 1.143: 1(-3.81,-1.27)
  round 1.651 hole 1.143: 2(-3.81,1.27) 3(-1.27,-1.27) 4(-1.27,1.27) 5(1.27,-1.27) 6(1.27,1.27) 7(3.81,-1.27) 8(3.81,1.27)
1571983-4
  rect 0.762x1.27 smd: 1(-1.905,-3.795) 2(-0.635,-3.795) 3(0.635,-3.795) 4(1.905,-3.795) 5(1.905,3.795) 6(0.635,3.795) 7(-0.635,3.795) 8(-1.905,3.795)
BAT_CONNECTOR_18650
  round 3.302 hole 3.302 unplated: (-27.805,0) (27.805,0)
  oval 1.397x2.54 hole 0.889x2.032: 1(36.45,0) 2(-36.45,0)
BGA265_0R8_14X14
  round 0.406 smd: A1(-6.4,-6.4) A2(-6.4,-5.6) A3(-6.4,-4.8) A4(-6.4,-4) A5(-6.4,-3.2) A6(-6.4,-2.4) A7(-6.4,-1.6) A8(-6.4,-0.8) A9(-6.4,0) A10(-6.4,0.8) A11(-6.4,1.6) A12(-6.4,2.4) A13(-6.4,3.2) A14(-6.4,4) A15(-6.4,4.8) A16(-6.4,5.6) A17(-6.4,6.4) B1(-5.6,-6.4) B2(-5.6,-5.6) B3(-5.6,-4.8) B4(-5.6,-4) B5(-5.6,-3.2) B6(-5.6,-2.4) B7(-5.6,-1.6) B8(-5.6,-0.8) B9(-5.6,0) B10(-5.6,0.8) B11(-5.6,1.6) B12(-5.6,2.4) B13(-5.6,3.2) B14(-5.6,4) B15(-5.6,4.8) B16(-5.6,5.6) B17(-5.6,6.4) C1(-4.8,-6.4) C2(-4.8,-5.6) C3(-4.8,-4.8) C4(-4.8,-4) C5(-4.8,-3.2) C6(-4.8,-2.4) C7(-4.8,-1.6) C8(-4.8,-0.8) C9(-4.8,0) C10(-4.8,0.8) C11(-4.8,1.6) C12(-4.8,2.4) C13(-4.8,3.2) C14(-4.8,4) C15(-4.8,4.8) C16(-4.8,5.6) C17(-4.8,6.4) D1(-4,-6.4) D2(-4,-5.6) D3(-4,-4.8) D4(-4,-4) D5(-4,-3.2) D6(-4,-2.4) D7(-4,-1.6) D8(-4,-0.8) D9(-4,0) D10(-4,0.8) D11(-4,1.6) D12(-4,2.4) D13(-4,3.2) D14(-4,4) D15(-4,4.8) D16(-4,5.6) D17(-4,6.4) E1(-3.2,-6.4) E2(-3.2,-5.6) E3(-3.2,-4.8) E4(-3.2,-4) E5(-3.2,-3.2) E6(-3.2,-2.4) E7(-3.2,-1.6) E8(-3.2,-0.8) E9(-3.2,0) E10(-3.2,0.8) E11(-3.2,1.6) E12(-3.2,2.4) E13(-3.2,3.2) E14(-3.2,4) E15(-3.2,4.8) E16(-3.2,5.6) E17(-3.2,6.4) F1(-2.4,-6.4) F2(-2.4,-5.6) F3(-2.4,-4.8) F4(-2.4,-4) F5(-2.4,-3.2) F13(-2.4,3.2) F14(-2.4,4) F15(-2.4,4.8) F16(-2.4,5.6) F17(-2.4,6.4) G1(-1.6,-6.4) G2(-1.6,-5.6) G3(-1.6,-4.8) G4(-1.6,-4) G5(-1.6,-3.2) G7(-1.6,-1.6) G8(-1.6,-0.8) G9(-1.6,0) G10(-1.6,0.8) G11(-1.6,1.6) G13(-1.6,3.2) G14(-1.6,4) G15(-1.6,4.8) G16(-1.6,5.6) G17(-1.6,6.4) H1(-0.8,-6.4) H2(-0.8,-5.6) H3(-0.8,-4.8) H4(-0.8,-4) H5(-0.8,-3.2) H7(-0.8,-1.6) H8(-0.8,-0.8) H9(-0.8,0) H10(-0.8,0.8) H11(-0.8,1.6) H13(-0.8,3.2) H14(-0.8,4) H15(-0.8,4.8) H16(-0.8,5.6) H17(-0.8,6.4) J1(0,-6.4) J2(0,-5.6) J3(0,-4.8) J4(0,-4) J5(0,-3.2) J7(0,-1.6) J8(0,-0.8) J9(0,0) J10(0,0.8) J11(0,1.6) J13(0,3.2) J14(0,4) J15(0,4.8) J16(0,5.6) J17(0,6.4) K1(0.8,-6.4) K2(0.8,-5.6) K3(0.8,-4.8) K4(0.8,-4) K5(0.8,-3.2) K7(0.8,-1.6) K8(0.8,-0.8) K9(0.8,0) K10(0.8,0.8) K11(0.8,1.6) K13(0.8,3.2) K14(0.8,4) K15(0.8,4.8) K16(0.8,5.6) K17(0.8,6.4) L1(1.6,-6.4) L2(1.6,-5.6) L3(1.6,-4.8) L4(1.6,-4) L5(1.6,-3.2) L7(1.6,-1.6) L8(1.6,-0.8) L9(1.6,0) L10(1.6,0.8) L11(1.6,1.6) L13(1.6,3.2) L14(1.6,4) L15(1.6,4.8) L16(1.6,5.6) L17(1.6,6.4) M1(2.4,-6.4) M2(2.4,-5.6) M3(2.4,-4.8) M4(2.4,-4) M5(2.4,-3.2) M13(2.4,3.2) M14(2.4,4) M15(2.4,4.8) M16(2.4,5.6) M17(2.4,6.4) N1(3.2,-6.4) N2(3.2,-5.6) N3(3.2,-4.8) N4(3.2,-4) N5(3.2,-3.2) N6(3.2,-2.4) N7(3.2,-1.6) N8(3.2,-0.8) N9(3.2,0) N10(3.2,0.8) N11(3.2,1.6) N12(3.2,2.4) N13(3.2,3.2) N14(3.2,4) N15(3.2,4.8) N16(3.2,5.6) N17(3.2,6.4) P1(4,-6.4) P2(4,-5.6) P3(4,-4.8) P4(4,-4) P5(4,-3.2) P6(4,-2.4) P7(4,-1.6) P8(4,-0.8) P9(4,0) P10(4,0.8) P11(4,1.6) P12(4,2.4) P13(4,3.2) P14(4,4) P15(4,4.8) P16(4,5.6) P17(4,6.4) R1(4.8,-6.4) R2(4.8,-5.6) R3(4.8,-4.8) R4(4.8,-4) R5(4.8,-3.2) R6(4.8,-2.4) R7(4.8,-1.6) R8(4.8,-0.8) R9(4.8,0) R10(4.8,0.8) R11(4.8,1.6) R12(4.8,2.4) R13(4.8,3.2) R14(4.8,4) R15(4.8,4.8) R16(4.8,5.6) R17(4.8,6.4) T1(5.6,-6.4) T2(5.6,-5.6) T3(5.6,-4.8) T4(5.6,-4) T5(5.6,-3.2) T6(5.6,-2.4) T7(5.6,-1.6) T8(5.6,-0.8) T9(5.6,0) T10(5.6,0.8) T11(5.6,1.6) T12(5.6,2.4) T13(5.6,3.2) T14(5.6,4) T15(5.6,4.8) T16(5.6,5.6) T17(5.6,6.4) U1(6.4,-6.4) U2(6.4,-5.6) U3(6.4,-4.8) U4(6.4,-4) U5(6.4,-3.2) U6(6.4,-2.4) U7(6.4,-1.6) U8(6.4,-0.8) U9(6.4,0) U10(6.4,0.8) U11(6.4,1.6) U12(6.4,2.4) U13(6.4,3.2) U14(6.4,4) U15(6.4,4.8) U16(6.4,5.6) U17(6.4,6.4)
CP-8-10
  oval 0.25x0.7 smd: 1(-0.75,-1.076) 2(-0.25,-1.076) 3(0.25,-1.076) 4(0.75,-1.076) 5(0.75,1.076) 6(0.25,1.076) 7(-0.25,1.076) 8(-0.75,1.076)
  rect 1.6x1 smd: 9(0,0)
CPH3225A
  rect 1.651x1.397 smd: 1(-1.227,0) 2(1.227,0)
CRF1206-FX-R020ELF
  rect 2.032x3.175 smd: 1(-2.5,0) 2(2.5,0)
DFN10DDB
  oval 0.254x0.762 smd: 1(-1,-0.95) 2(-0.5,-0.95) 3(0,-0.95) 4(0.5,-0.95) 5(1,-0.95) 6(1,0.95) 7(0.5,0.95) 8(0,0.95) 9(-0.5,0.95) 10(-1,0.95)
  rect 2.388x0.635 smd: 11(0,0)
DFN16X10X050X2LEAD
  rect 0.635x1.016 smd: 1(-0.612,0) 2(0.612,0)
DFN_8P
  oval 0.254x0.762 smd: 1(-0.75,-1.47) 2(-0.25,-1.47) 3(0.25,-1.47) 4(0.75,-1.47) 5(0.75,1.47) 6(0.25,1.47) 7(-0.25,1.47) 8(-0.75,1.47)
  rect 2.388x1.651 smd: 9(0,0)
DFN_060X030X025MM_2LEAD
  rect 0.254x0.279 smd: 1(-0.217,0) 2(0.217,0)
DIP_2X20X_254
  rect 1.524x1.524 hole 1.016: 1(-24.13,-1.27)
  round 1.524 hole 1.016: 2(-24.13,1.27) 3(-21.59,-1.27) 4(-21.59,1.27) 5(-19.05,-1.27) 6(-19.05,1.27) 7(-16.51,-1.27) 8(-16.51,1.27) 9(-13.97,-1.27) 10(-13.97,1.27) 11(-11.43,-1.27) 12(-11.43,1.27) 13(-8.89,-1.27) 14(-8.89,1.27) 15(-6.35,-1.27) 16(-6.35,1.27) 17(-3.81,-1.27) 18(-3.81,1.27) 19(-1.27,-1.27) 20(-1.27,1.27) 21(1.27,-1.27) 22(1.27,1.27) 23(3.81,-1.27) 24(3.81,1.27) 25(6.35,-1.27) 26(6.35,1.27) 27(8.89,-1.27) 28(8.89,1.27) 29(11.43,-1.27) 30(11.43,1.27) 31(13.97,-1.27) 32(13.97,1.27) 33(16.51,-1.27) 34(16.51,1.27) 35(19.05,-1.27) 36(19.05,1.27) 37(21.59,-1.27) 38(21.59,1.27) 39(24.13,-1.27) 40(24.13,1.27)
EMSTAT_PICO
  rect 2.997x1.524 smd: 1(-14.86,5.08) 2(-14.86,2.54) 3(-14.86,0) 4(-14.86,-2.54) 5(-14.86,-5.08) 15(14.86,-5.08) 16(14.86,-2.54) 17(14.86,0) 18(14.86,2.54) 19(14.86,5.08)
  rect 1.524x2.997 smd: 6(-11.43,-8.51) 7(-8.89,-8.51) 8(-6.35,-8.51) 9(-3.81,-8.51) 10(-1.27,-8.51) 11(1.27,-8.51) 12(3.81,-8.51) 13(6.35,-8.51) 14(8.89,-8.51) 20(8.89,8.51) 21(6.35,8.51) 22(3.81,8.51) 23(1.27,8.51) 24(-1.27,8.51) 25(-3.81,8.51) 26(-6.35,8.51) 27(-8.89,8.51) 28(-11.43,8.51)
EPG_0B_305_HLN
  round 1.321 hole 0.813: 1(-3.81,-1.27) 2(-1.27,-1.27) 3(1.27,-1.27) 4(1.27,1.27) 5(-1.27,1.27) 7(-3.81,-3.81) 8(3.81,-3.81) 9(3.81,3.81) 10(-3.81,3.81)
FBGA90_0R8_8X13
  round 0.406 smd: A1(-5.6,-3.2) A2(-5.6,-2.4) A3(-5.6,-1.6) A7(-5.6,1.6) A8(-5.6,2.4) A9(-5.6,3.2) B1(-4.8,-3.2) B2(-4.8,-2.4) B3(-4.8,-1.6) B7(-4.8,1.6) B8(-4.8,2.4) B9(-4.8,3.2) C1(-4,-3.2) C2(-4,-2.4) C3(-4,-1.6) C7(-4,1.6) C8(-4,2.4) C9(-4,3.2) D1(-3.2,-3.2) D2(-3.2,-2.4) D3(-3.2,-1.6) D7(-3.2,1.6) D8(-3.2,2.4) D9(-3.2,3.2) E1(-2.4,-3.2) E2(-2.4,-2.4) E3(-2.4,-1.6) E7(-2.4,1.6) E8(-2.4,2.4) E9(-2.4,3.2) F1(-1.6,-3.2) F2(-1.6,-2.4) F3(-1.6,-1.6) F7(-1.6,1.6) F8(-1.6,2.4) F9(-1.6,3.2) G1(-0.8,-3.2) G2(-0.8,-2.4) G3(-0.8,-1.6) G7(-0.8,1.6) G8(-0.8,2.4) G9(-0.8,3.2) H1(0,-3.2) H2(0,-2.4) H3(0,-1.6) H7(0,1.6) H8(0,2.4) H9(0,3.2) J1(0.8,-3.2) J2(0.8,-2.4) J3(0.8,-1.6) J7(0.8,1.6) J8(0.8,2.4) J9(0.8,3.2) K1(1.6,-3.2) K2(1.6,-2.4) K3(1.6,-1.6) K7(1.6,1.6) K8(1.6,2.4) K9(1.6,3.2) L1(2.4,-3.2) L2(2.4,-2.4) L3(2.4,-1.6) L7(2.4,1.6) L8(2.4,2.4) L9(2.4,3.2) M1(3.2,-3.2) M2(3.2,-2.4) M3(3.2,-1.6) M7(3.2,1.6) M8(3.2,2.4) M9(3.2,3.2) N1(4,-3.2) N2(4,-2.4) N3(4,-1.6) N7(4,1.6) N8(4,2.4) N9(4,3.2) P1(4.8,-3.2) P2(4.8,-2.4) P3(4.8,-1.6) P7(4.8,1.6) P8(4.8,2.4) P9(4.8,3.2) R1(5.6,-3.2) R2(5.6,-2.4) R3(5.6,-1.6) R7(5.6,1.6) R8(5.6,2.4) R9(5.6,3.2)
FPC-40P_05MM
  rect 1.778x2.235 smd: (-11.65,1.625) (11.65,1.625)
  rect 0.254x1.321 smd: 1(9.75,-1.625) 2(9.25,-1.625) 3(8.75,-1.625) 4(8.25,-1.625) 5(7.75,-1.625) 6(7.25,-1.625) 7(6.75,-1.625) 8(6.25,-1.625) 9(5.75,-1.625) 10(5.25,-1.625) 11(4.75,-1.625) 12(4.25,-1.625) 13(3.75,-1.625) 14(3.25,-1.625) 15(2.75,-1.625) 16(2.25,-1.625) 17(1.75,-1.625) 18(1.25,-1.625) 19(0.75,-1.625) 20(0.25,-1.625) 21(-0.25,-1.625) 22(-0.75,-1.625) 23(-1.25,-1.625) 24(-1.75,-1.625) 25(-2.25,-1.625) 26(-2.75,-1.625) 27(-3.25,-1.625) 28(-3.75,-1.625) 29(-4.25,-1.625) 30(-4.75,-1.625) 31(-5.25,-1.625) 32(-5.75,-1.625) 33(-6.25,-1.625) 34(-6.75,-1.625) 35(-7.25,-1.625) 36(-7.75,-1.625) 37(-8.25,-1.625) 38(-8.75,-1.625) 39(-9.25,-1.625) 40(-9.75,-1.625)
GND12
  round 0.635 hole 0.305: 1(0,0)
HC_06_34
  rect 1.651x1.143 smd: 1(-6.6,6.25) 2(-6.6,4.75) 3(-6.6,3.25) 4(-6.6,1.75) 5(-6.6,0.25) 6(-6.6,-1.25) 7(-6.6,-2.75) 8(-6.6,-4.25) 9(-6.6,-5.75) 10(-6.6,-7.25) 11(-6.6,-8.75) 12(-6.6,-10.25) 13(-6.6,-11.75) 22(6.6,-11.75) 23(6.6,-10.25) 24(6.6,-8.75) 25(6.6,-7.25) 26(6.6,-5.75) 27(6.6,-4.25) 28(6.6,-2.75) 29(6.6,-1.25) 30(6.6,0.25) 31(6.6,1.75) 32(6.6,3.25) 33(6.6,4.75) 34(6.6,6.25)
  rect 1.143x1.651 smd: 14(-5.25,-13.6) 15(-3.75,-13.6) 16(-2.25,-13.6) 17(-0.75,-13.6) 18(0.75,-13.6) 19(2.25,-13.6) 20(3.75,-13.6) 21(5.25,-13.6)
HOLE87-197
  round 5.004 hole 2.21: 1(0,0)
HR911105A
  round 3.251 hole 3.251 unplated: (-5.715,1.995) (5.715,1.995)
  rect 1.397x1.397 hole 0.889: 1(4.445,-4.355)
  round 1.397 hole 0.889: 2(3.175,-6.895) 3(1.905,-4.355) 4(0.635,-6.895) 5(-0.635,-4.355) 6(-1.905,-6.895) 7(-3.175,-4.355) 8(-4.445,-6.895)
  round 1.524 hole 1.016: 9(6.625,6.895) 10(4.085,6.895) 11(-4.085,6.895) 12(-6.625,6.895)
  round 2.159 hole 1.651: 13(7.745,-1.055) 14(-7.745,-1.055)
HSDC10-1614B
  rect 0.711x1.219 smd: 1(2.775,7.975) 2(1.675,7.975) 3(0.575,7.975) 4(-0.525,7.975) 5(-1.625,7.975) 6(-2.725,7.975) 7(-3.825,7.975) 8(-4.925,7.975) 9(-5.891,7.975)
  rect 1.016x1.219 smd: 10(4.325,7.975) 11(-6.825,3.675)
  rect 1.016x0.813 smd: 12(-6.825,-2.526)
  rect 1.016x2.794 smd: 13(-6.825,-6.675)
  rect 1.778x1.905 smd: 14(6.675,-7.125)
HSOD323A
  rect 1.118x0.813 smd: 1(1.372,0) 2(-1.372,0)
HSOT-SC70-DCK
  rect 0.381x1.143 smd: 1(-0.65,-0.94) 2(0,-0.94) 3(0.65,-0.94) 4(0.65,0.94) 5(-0.65,0.94)
HSX2-0302
  rect 1.016x1.778 smd: 1(-1.25,0) 2(1.25,0)
INF-PG-DSO-8-3_N
  oval 1.778x0.635 smd: 1(-2.6,1.905) 2(-2.6,0.635) 3(-2.6,-0.635) 4(-2.6,-1.905) 5(2.6,-1.905) 6(2.6,-0.635) 7(2.6,0.635) 8(2.6,1.905)
LQFP48-0M5-JL
  rect 0.254x1.524 smd: 1(-2.75,-4.2) 2(-2.25,-4.2) 3(-1.75,-4.2) 4(-1.25,-4.2) 5(-0.75,-4.2) 6(-0.25,-4.2) 7(0.25,-4.2) 8(0.75,-4.2) 9(1.25,-4.2) 10(1.75,-4.2) 11(2.25,-4.2) 12(2.75,-4.2) 25(2.75,4.2) 26(2.25,4.2) 27(1.75,4.2) 28(1.25,4.2) 29(0.75,4.2) 30(0.25,4.2) 31(-0.25,4.2) 32(-0.75,4.2) 33(-1.25,4.2) 34(-1.75,4.2) 35(-2.25,4.2) 36(-2.75,4.2)
  rect 1.524x0.254 smd: 13(4.2,-2.75) 14(4.2,-2.25) 15(4.2,-1.75) 16(4.2,-1.25) 17(4.2,-0.75) 18(4.2,-0.25) 19(4.2,0.25) 20(4.2,0.75) 21(4.2,1.25) 22(4.2,1.75) 23(4.2,2.25) 24(4.2,2.75) 37(-4.2,2.75) 38(-4.2,2.25) 39(-4.2,1.75) 40(-4.2,1.25) 41(-4.2,0.75) 42(-4.2,0.25) 43(-4.2,-0.25) 44(-4.2,-0.75) 45(-4.2,-1.25) 46(-4.2,-1.75) 47(-4.2,-2.25) 48(-4.2,-2.75)
PFL1005
  rect 0.406x0.66 smd: 1(-0.483,0) 2(0.483,0)
QFN-14
  custom 0.231x0.231 smd: (-1.338,0)
  rect 0.254x1.143 smd: 1(-1,-1.25) 2(-0.5,-1.25) 3(0,-1.25) 4(0.5,-1.25) 5(1,-1.25) 8(1,1.25) 9(0.5,1.25) 10(0,1.25) 11(-0.5,1.25) 12(-1,1.25)
  rect 0.762x0.254 smd: 6(1.45,-0.25) 7(1.45,0.25) 13(-1.45,0.25) 14(-1.45,-0.25)
  rect 0.559x0.559 smd: 15(0.125,0)
QFN_24P
  oval 0.254x0.762 smd: 1(-1.25,-1.98) 2(-0.75,-1.98) 3(-0.25,-1.98) 4(0.25,-1.98) 5(0.75,-1.98) 6(1.25,-1.98) 13(1.25,1.98) 14(0.75,1.98) 15(0.25,1.98) 16(-0.25,1.98) 17(-0.75,1.98) 18(-1.25,1.98)
  oval 0.762x0.254 smd: 7(1.98,-1.25) 8(1.98,-0.75) 9(1.98,-0.25) 10(1.98,0.25) 11(1.98,0.75) 12(1.98,1.25) 19(-1.98,1.25) 20(-1.98,0.75) 21(-1.98,0.25) 22(-1.98,-0.25) 23(-1.98,-0.75) 24(-1.98,-1.25)
  rect 2.743x2.743 smd: 25(0,0)
RQM0029A-MFG
  custom 0.175x0.175 smd: 1(-1.35,1.6) 9(-1.401,-1.6) 16(1.401,-1.6) 24(1.35,1.6)
  rect 0.61x0.203 smd: 2(-1.9,1.2) 3(-1.9,0.8) 4(-1.9,0.4) 5(-1.9,0) 6(-1.9,-0.4) 7(-1.9,-0.8) 8(-1.9,-1.2) 20(1.9,0) 21(1.9,0.4) 22(1.9,0.8) 23(1.9,1.2)
  rect 0.203x0.61 smd: 10(-1,-1.9) 11(-0.6,-1.9) 12(-0.2,-1.9) 13(0.2,-1.9) 14(0.6,-1.9) 15(1,-1.9)
  rect 0.711x0.203 smd: 17(1.85,-1.2)
  rect 0.66x0.203 smd: 18(1.875,-0.8)
  rect 0.686x0.203 smd: 19(1.86,-0.4)
  rect 0.203x1.016 smd: 25(0.9,1.7) 26(0.45,1.7) 27(0,1.7) 28(-0.45,1.7)
  rect 0.203x0.965 smd: 29(-0.9,1.725)
SC0402
  rect 0.508x0.508 smd: 1(-0.406,0) 2(0.406,0)
SC0402-BGA
  custom 0.119x0.119 smd: 1(-0.47,0) 2(0.47,0)
SC0603
  rect 0.762x0.813 smd: 1(-0.699,0) 2(0.699,0)
SC0805
  rect 0.991x1.27 smd: 1(-0.813,0) 2(0.813,0)
SC7343
  rect 2.667x2.413 smd: 1(-3.233,0) 2(3.233,0)
SL0402
  rect 0.483x0.508 smd: 1(-0.394,0) 2(0.394,0)
SL1008H
  rect 1.321x2.032 smd: 1(-1.26,0) 2(1.26,0)
SLED0603
  rect 0.813x0.864 smd: 1(-0.675,0) 2(0.675,0)
SMD_2520
  rect 1.143x0.914 smd: 1(-0.9,-0.7) 2(0.9,-0.7) 3(0.9,0.7) 4(-0.9,0.7)
SMD_3225
  rect 1.397x1.219 smd: 1(-1.1,-0.95) 2(1.1,-0.95) 3(1.1,0.95) 4(-1.1,0.95)
SMT2
  rect 2.032x1.27 smd: 1(-3,0) 2(3,0)
SOD123
  rect 1.27x0.813 smd: 1(1.75,0) 2(-1.75,0)
SOD123F
  rect 1.27x0.813 smd: 1(-1.75,0) 2(1.75,0)
SOT23
  rect 1.016x1.27 smd: 1(-1.016,-1.143) 2(1.016,-1.143) 3(0,1.143)
SR0402
  rect 0.508x0.508 smd: 1(-0.406,0) 2(0.406,0)
SR0603
  rect 0.711x0.813 smd: 1(-0.737,0) 2(0.737,0)
SR0805
  rect 0.838x1.143 smd: 1(-0.927,0) 2(0.927,0)
SR1206
  rect 1.295x1.854 smd: 1(-1.346,0) 2(1.346,0)
SR2512
  rect 1.524x3.175 smd: 1(-3.302,0) 2(3.302,0)
TSOT23-8
  rect 0.356x1.27 smd: 1(-0.975,-1.275) 2(-0.325,-1.275) 3(0.325,-1.275) 4(0.975,-1.275) 5(0.975,1.275) 6(0.325,1.275) 7(-0.325,1.275) 8(-0.975,1.275)
unnamed#2
  round 1.016 smd: 1(0,0)
USB_C_24P
  rect 0.254x0.711 smd: A1(-3,3.285) A2(-2.5,3.285) A3(-2,3.285) A4(-1.5,3.285) A5(-1,3.285) A6(-0.5,3.285) A7(0.5,3.285) A8(1,3.285) A9(1.5,3.285) A10(2,3.285) A11(2.5,3.285) A12(3,3.285) B2(2.25,1.585) B3(1.75,1.585) B4(1.25,1.585) B5(0.75,1.585) B6(0.25,1.585) B7(-0.25,1.585) B8(-0.75,1.585) B9(-1.25,1.585) B10(-1.75,1.585) B11(-2.25,1.585)
  rect 0.914x0.711 smd: B1(3.05,1.585) B12(-3.05,1.585)
  oval 1.016x2.159 hole 0.635x1.651: M1(-4.32,2.475) M2(4.32,2.475)
  oval 1.143x3.6 hole 0.635x2.159: M3(-4.62,-2.885) M4(4.62,-2.885)
WSON_8P_8X6MM
  rect 4.343x3.454 smd: (0,0)
  oval 0.635x1.016 smd: 1(-1.905,-3.96) 2(-0.635,-3.96) 3(0.635,-3.96) 4(1.905,-3.96) 5(1.905,3.96) 6(0.635,3.96) 7(-0.635,3.96) 8(-1.905,3.96)
XAL5030
  rect 1.524x4.699 smd: 1(-1.7,0) 2(1.7,0)
XEL4030
  rect 1.321x4.369 smd: 1(-1.295,0) 2(1.295,0)

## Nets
1V2: C224.2(B) C351.1 C352.1 C353.1 C1795.1 C1796.1 C1797.1 L10.2 LB5.1 R86.1 U26.5
2V5: C1951.1 C1952.2(B) C2017.1 C2018.2(B) C2019.2(B) R1863.1 U1.M1 U141.1 U141.2
3V3: C75.1 C510.1 C914.2(B) C915.1 C1240.2(B) C1241.1 C1246.2(B) C1247.1 C1599.2(B) C1606.1 C1607.1 C1608.1 C1609.1 C1610.1 C1812.1 C1813.1 C1814.1 C1815.2(B) C1868.1 C1904.1 C1911.2(B) C1912.1 C1913.1 C1966.1 C1967.1 C1968.1 C1969.2(B) C1999.1 C2020.1 C2021.1 C2022.2(B) D25.1 D74.2 D117.2 D118.2 D121.2 D122.2 J6.1 J56.4 J63.1 J78.2 L53.2 L61.1 L63.1 LB7.1 LB8.1 LB9.1 Q1.2(S) Q50.2(S) R118.1 R135.1 R898.1 R1373.2(B) R1508.1 R1612.1 R1737.1 R1740.1 R1741.1 R1743.1 R1753.1 R1754.1 R1759.1 R1760.1 R1797.1 R1800.1 R1806.1 R1807.1 R1817.1 R1818.1 R1819.1 R1820.1 R1828.1 R1835.2(B) R1837.1 R1839.1 R1840.1 R1842.1 R1843.1 R1862.1 R1865.1 R1866.1 S7.2 S10.2 U77.8 U132.5 U135.12 U140.5 U141.7(VIN2) U141.8
3V9: C46.2(B) C94.1 C1905.1 C1907.2(B) C2010.2(B) C2011.2(B) R14.1 U4.1 U4.2 U134.27
5V0: C42.1 C44.2(B) C458.2(B) C459.1 C461.1 C462.1 C463.1 C464.2(B) C1289.1 C1290.2(B) C1580.1 C1581.1 C1593.1 C1594.2(B) C1780.1 C1781.1 C1782.1 C1783.1 C1784.1 C1785.1 C1786.1 C1788.1 C2009.1 J1.1 J1.2 J2.1 J2.2 L43.1 L50.1 L60.2 R20.1 R50.2(B) R1603.1 R1606.2(B) R1830.1 U4.7(VIN2) U4.8
5V0_VBUS_0: R522.1 R1673.2(B)
AGND: C46.1 C94.2(B) C185.2(B) C1905.2(B) C1907.1 C1908.2(B) C2010.1 C2011.1 J74.4 J75.2 J75.7 J75.8 J75.9 J75.10 J76.4 J76.5 J78.16 R267.2(B) R1739.2(B) R1742.2(B) R1844.2(B) U4.4 U4.9 U134.15
AVDD1V8: C81.1 C332.1 C1953.2(B) C1954.2(B) C2008.1 J3.4 J3.5 U3.1 U3.2 U3.9
GND: C4.2(B) C42.2(B) C43.2(B) C44.1 C197.2(B) C223.1 C224.1 C228.1 C229.1 C230.1 C231.1 C271.1 C273.1 C274.1 C282.1 C283.1 C284.1 C285.1 C286.1 C287.1 C288.1 C289.1 C290.1 C339.1 C341.2(B) C342.1 C343.1 C344.1 C345.1 C351.2(B) C352.2(B) C353.2(B) C354.1 C355.1 C356.1 C402.2(B) C413.2(B) C432.1 C433.1 C458.1 C459.2(B) C461.2(B) C462.2(B) C463.2(B) C464.1 C510.2(B) C511.2(B) C512.2(B) C517.2(B) C595.2(B) C616.1 C914.1 C915.2(B) C1240.1 C1241.2(B) C1246.1 C1247.2(B) C1289.2(B) C1290.1 C1291.2(B) C1485.1 C1499.1 C1502.1 C1503.1 C1504.1 C1505.1 C1506.1 C1507.1 C1521.2(B) C1542.1 C1543.1 C1544.1 C1545.1 C1573.2(B) C1574.1 C1575.2(B) C1580.2(B) C1581.2(B) C1589.1 C1590.2(B) C1591.2 C1592.2(B) C1593.2(B) C1594.1 C1595.2(B) C1597.1 C1599.1 C1605.2(B) C1606.2(B) C1607.2(B) C1608.2 C1609.2(B) C1610.2(B) C1623.2(B) C1624.1 C1639.1 C1640.2(B) C1643.2(B) C1644.2(B) C1645.2(B) C1646.2(B) C1647.2(B) C1648.2(B) C1649.2(B) C1650.2(B) C1651.2(B) C1652.2(B) C1689.2(B) C1691.2(B) C1692.2(B) C1693.2(B) C1694.2(B) C1695.2(B) C1696.2(B) C1697.2(B) C1698.2(B) C1699.2(B) C1700.2(B) C1771.1 C1772.2(B) C1773.1 C1774.2(B) C1775.2(B) C1776.2(B) C1777.2(B) C1778.1 C1780.2(B) C1781.2(B) C1782.2(B) C1783.2(B) C1784.2(B) C1785.2(B) C1786.2 C1788.2 C1790.1 C1791.1 C1795.2(B) C1796.2(B) C1797.2(B) C1812.2(B) C1813.2(B) C1814.2(B) C1815.1 C1818.2(B) C1819.2(B) C1820.2(B) C1821.1 C1868.2(B) C1875.1 C1881.2(B) C1882.2(B) C1883.2(B) C1884.2(B) C1909.2(B) C1910.2(B) C1911.1 C1912.2(B) C1913.2(B) C1916.2(B) C1918.1 C1919.1 C1920.1 C1921.1 C1922.1 C1923.1 C1924.1 C1925.1 C1926.1 C1927.1 C1928.1 C1929.1 C1930.1 C1931.1 C1945.1 C1946.1 C1947.1 C1950.2(B) C1951.2(B) C1952.1 C1955.1 C1956.2(B) C1957.2(B) C1958.1 C1964.2(B) C1965.2(B) C1966.2(B) C1967.2(B) C1968.2(B) C1969.1 C1970.2(B) C1971.2(B) C1972.2(B) C1973.1 C1974.1 C1975.2(B) C1976.1 C1977.2(B) C1978.1 C1980.2(B) C1999.2(B) C2000.1 C2001.2(B) C2002.1 C2003.1 C2004.1 C2005.1 C2006.1 C2007.1 C2009.2(B) C2012.2(B) C2013.2(B) C2015.2 C2016.2 C2017.2(B) C2018.1 C2019.1 C2020.2(B) C2021.2(B) C2022.1 C2023.1 C2024.1 C2025.1 D76.3 D96.2 D106.2 D107.2 D108.2 D109.2 D113.1(K) D114.3 D133.1(K) J1.3 J1.4 J1.29 J1.31 J1.36 J2.3 J2.4 J2.29 J2.31 J2.36 J3.8 J3.13 J3.14 J6.2 J7.2(-) J8.6(VSS) J8.10 J8.11 J8.12 J8.13 J8.14 J56.2 J56.10 J63.4 J73.A1 J73.A12 J73.B1 J73.B12 J73.M1 J73.M2 J73.M3 J73.M4 J86.2 M1.1(GND1) M2.1(GND1) M3.1(GND1) Q2.2(S) Q10.2(S) Q36.2(S) R116.2(B) R117.2(B) R142.2(B) R1359.2(B) R1361.1 R1367.2(B) R1370.1 R1475.2(B) R1523.2(B) R1525.2(B) R1553.2(B) R1554.1 R1602.2(B) R1609.2(B) R1610.2(B) R1696.2(B) R1697.2(B) R1744.2(B) R1745.2(B) R1748.2(B) R1767.2(B) R1798.1 R1799.2(B) R1802.2(B) R1803.2(B) R1826.2(B) R1829.2(B) R1838.2(B) R1841.2(B) R1844.1 R1845.1 R1859.1 R1864.2(B) R1869.2(B) S4.2 U1.A1 U1.A17 U1.B2 U1.B6 U1.C10 U1.C13 U1.C16 U1.F2(VSSIO_SD) U1.G2 U1.G7 U1.G8 U1.G9 U1.G10 U1.G11 U1.G16 U1.H7 U1.H8 U1.H9 U1.H10 U1.H11 U1.J3 U1.J7 U1.J8 U1.J9 U1.J10 U1.J11 U1.J16 U1.J17 U1.K7 U1.K8 U1.K9 U1.K10 U1.K11 U1.K15 U1.L7 U1.L8 U1.L9 U1.L10 U1.L11 U1.L15 U1.M15 U1.N1 U1.N16 U1.P1 U1.R4 U1.R8 U1.T12 U1.U1 U1.U17 U2.A3 U2.B3 U2.B8 U2.C1 U2.D1 U2.E9 U2.F1 U2.L3 U2.L9 U2.M1 U2.N1 U2.P3 U2.P8 U2.R3 U3.10 U3.15 U3.33 U3.39 U3.44 U8.1 U8.12 U8.13 U8.14 U26.4 U26.6 U37.6 U37.7 U37.10 U37.11 U77.4 U117.19 U117.22 U117.25 U128.2 U128.3 U128.7 U128.9 U132.4 U132.6 U133.27 U134.8 U134.28 U135.13(56) U140.3 U141.4 U141.9 X3.2 X3.4(GND2) X5.2
GND_SIGNAL: C81.2(B) C332.2 C1953.1 C1954.1 C1961.1 C1962.1 C2008.2 R1766.2(B) R1845.2(B) U3.5 U3.6 U3.46 U3.47
VBAT: C616.2(B) C1573.1 C1574.2(B) C1650.1 C1651.1 C1652.1 C1700.1 C2003.2(B) C2015.1 C2016.1 D25.3 R1446.2(B) R1519.1 R1698.2(B) U1.B1 U128.1 U133.22 U133.23
VBUS: C1542.2(B) C1543.2(B) C1544.2(B) C1545.2(B) F4.1 J73.A4 J73.A9 J73.B4 J73.B9(VBUS3)
VBUS_MAX: R1358.1 R1359.1 U117.2
VBUS_MIN: R1360.1 R1361.2(B) U117.1
VBUS_OUT: C1510.1 C1689.1 C1691.1 C1692.1 C1693.1 C1694.1 C1881.1 C1882.1 C1883.1 C1884.1 Q22.5 Q22.6 U117.11 U133.2 U133.3(VBUS#3) U133.8 U133.9
VCC_COMB: C1643.1 C1644.1 C1645.1 C1646.1 C1647.1 C1648.1 C1649.1 C1699.1 C1879.2(B) Q35.1 Q35.2 Q35.3(SOURCE#3) R324.1 R1460.1 R1461.2(B) R1469.1 R1695.2(B) U133.25
